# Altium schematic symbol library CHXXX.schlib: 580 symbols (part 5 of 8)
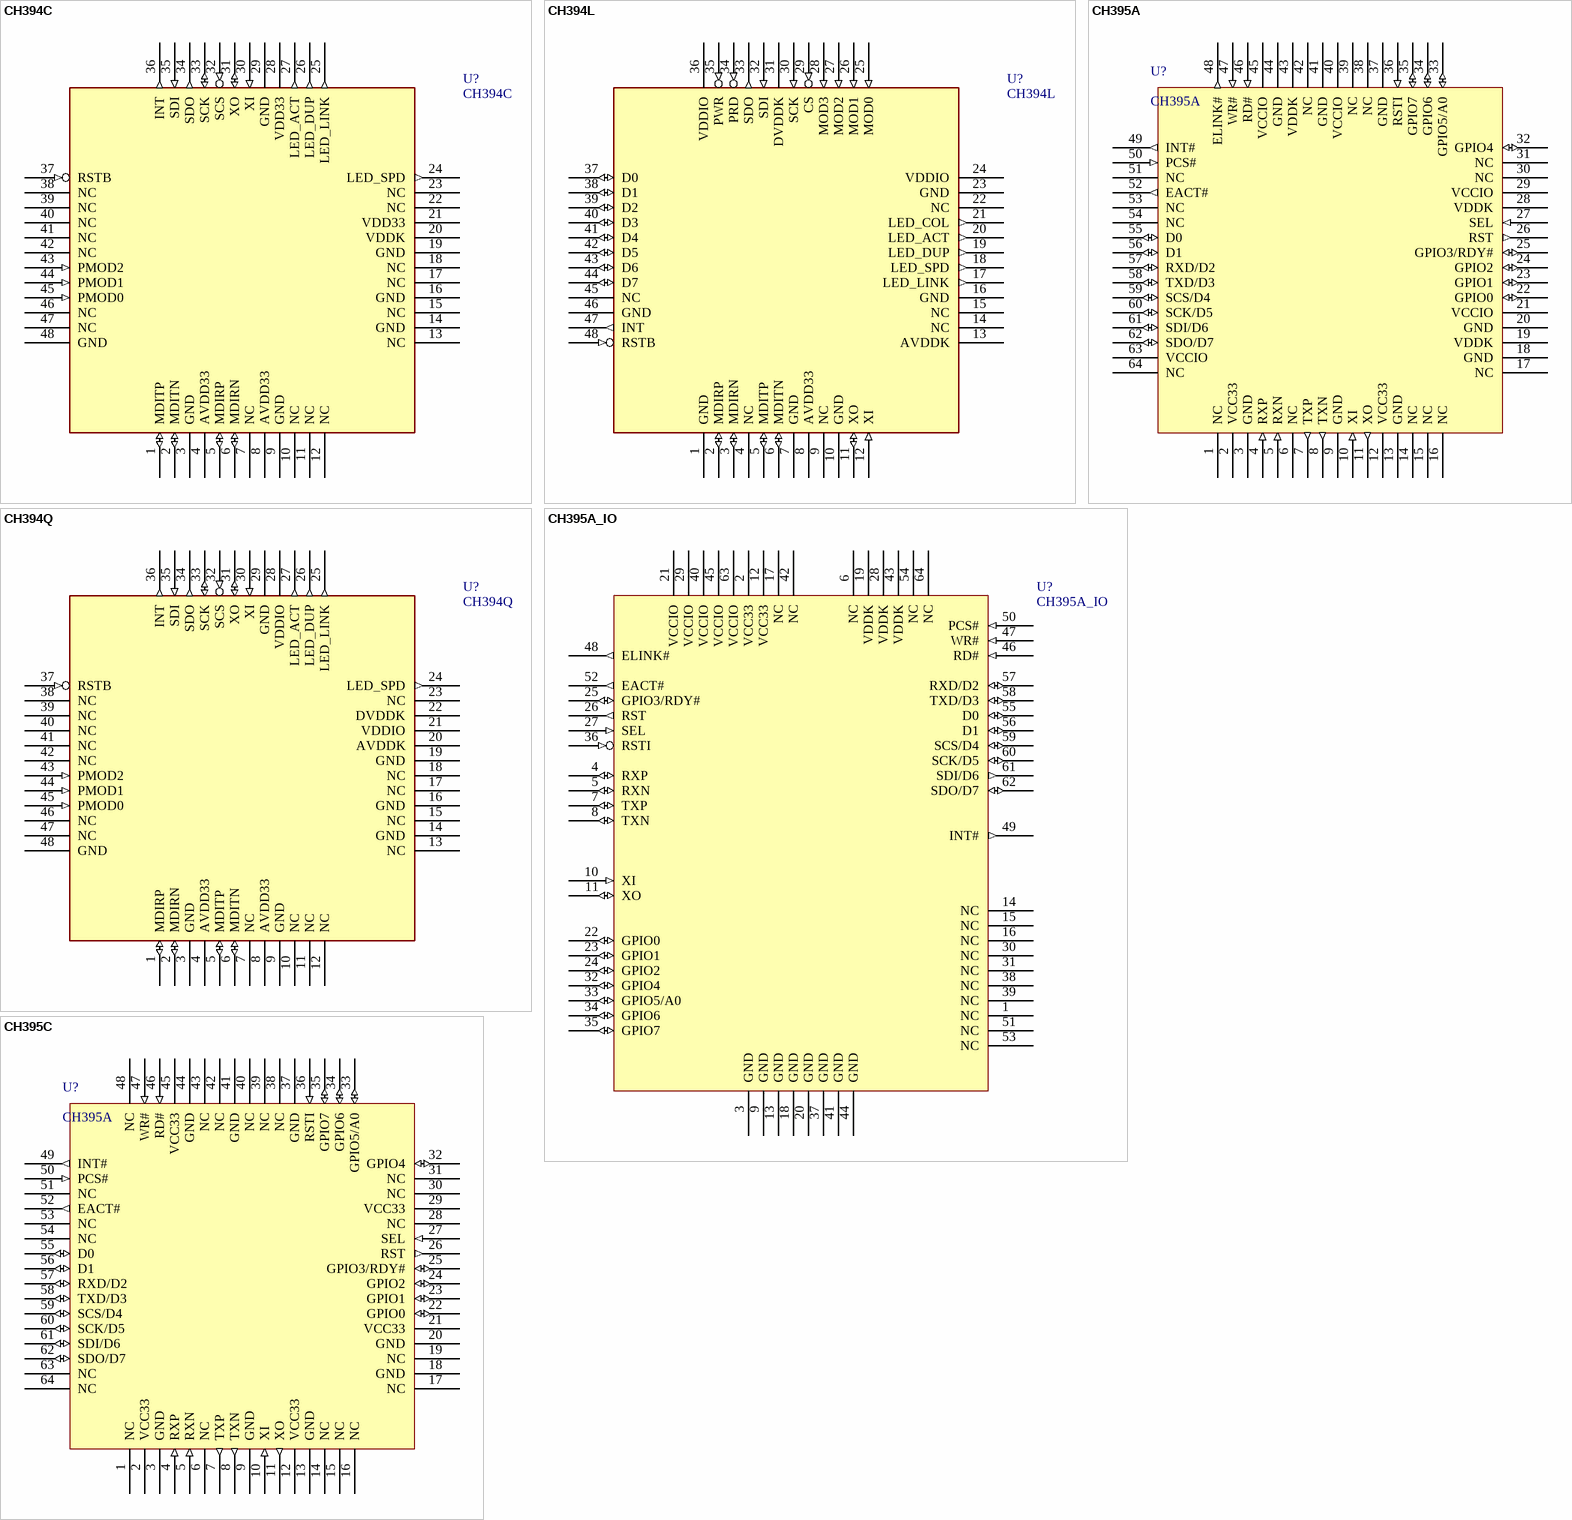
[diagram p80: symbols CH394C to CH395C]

## CH394Q
designator U?
TCP/IP embedded 10M/100Mbps ethernet controller for MCU connecting internet
footprint LQFP48 (Footprint not found)
pins: 1 MDIRP (io), 2 MDIRN (io), 3 GND (power), 4 AVDD33 (power), 5 MDITP (io), 6 MDITN (io), 7 NC, 8 AVDD33 (power), 9 GND (power), 10 NC, 11 NC, 12 NC, 13 NC, 14 GND (power), 15 NC, 16 GND (power), 17 NC, 18 NC, 19 GND (power), 20 AVDDK (power), 21 VDDIO (power), 22 DVDDK (power), 23 NC, 24 LED_SPD (out), 25 LED_LINK (out), 26 LED_DUP (out), 27 LED_ACT (out), 28 VDDIO (power), 29 GND (power), 30 XI (in), 31 XO (io), 32 SCS (in), 33 SCK (io), 34 SDO (out), 35 SDI (in), 36 INT (out), 37 RSTB (in), 38 NC, 39 NC, 40 NC, 41 NC, 42 NC, 43 PMOD2 (in), 44 PMOD1 (in), 45 PMOD0 (in), 46 NC, 47 NC, 48 GND (power)

## CH395A
designator U?
TCP/IP embedded 100Mbps ethernet controller for MCU connecting internet
footprint LQFP64M_10x10 (Footprint not found)
pins: 1 NC, 2 VCC33 (power), 3 GND, 4 RXP (in), 5 RXN (in), 6 NC, 7 TXP (out), 8 TXN (out), 9 GND (power), 10 XI (in), 11 XO (out), 12 VCC33 (power), 13 GND (power), 14 NC, 15 NC, 16 NC, 17 NC, 18 GND (power), 19 VDDK (power), 20 GND (power), 21 VCCIO (power), 22 GPIO0 (io), 23 GPIO1 (io), 24 GPIO2 (io), 25 GPIO3/RDY# (io), 26 RST (out), 27 SEL (in), 28 VDDK (power), 29 VCCIO (power), 30 NC, 31 NC, 32 GPIO4 (io), 33 GPIO5/A0 (io), 34 GPIO6 (io), 35 GPIO7 (io), 36 RSTI (in), 37 GND (power), 38 NC, 39 NC, 40 VCCIO (power), 41 GND (power), 42 NC, 43 VDDK (power), 44 GND (power), 45 VCCIO (power), 46 RD# (in), 47 WR# (in), 48 ELINK# (out), 49 INT# (out), 50 PCS# (in), 51 NC, 52 EACT# (out), 53 NC, 54 NC, 55 D0 (io), 56 D1 (io), 57 RXD/D2 (io), 58 TXD/D3 (io), 59 SCS/D4 (io), 60 SCK/D5 (io), 61 SDI/D6 (io), 62 SDO/D7 (io), 63 VCCIO (power), 64 NC

## CH395A_IO
designator U?
TCP/IP embedded 100Mbps ethernet controller for MCU connecting internet
footprint LQFP64M_10X10
pins: 1 NC, 2 VCC33 (power), 3 GND (power), 4 RXP (io), 5 RXN (io), 6 NC, 7 TXP (io), 8 TXN (io), 9 GND (power), 10 XI (in), 11 XO (io), 12 VCC33 (power), 13 GND (power), 14 NC, 15 NC, 16 NC, 17 NC, 18 GND (power), 19 VDDK (power), 20 GND (power), 21 VCCIO (power), 22 GPIO0 (io), 23 GPIO1 (io), 24 GPIO2 (io), 25 GPIO3/RDY# (io), 26 RST (out), 27 SEL (in), 28 VDDK (power), 29 VCCIO (power), 30 NC, 31 NC, 32 GPIO4 (io), 33 GPIO5/A0 (io), 34 GPIO6 (io), 35 GPIO7 (io), 36 RSTI (in), 37 GND (power), 38 NC, 39 NC, 40 VCCIO (power), 41 GND (power), 42 NC, 43 VDDK (power), 44 GND (power), 45 VCCIO (power), 46 RD# (in), 47 WR# (in), 48 ELINK# (out), 49 INT# (out), 50 PCS# (in), 51 NC, 52 EACT# (out), 53 NC, 54 NC, 55 D0 (io), 56 D1 (io), 57 RXD/D2 (io), 58 TXD/D3 (io), 59 SCS/D4 (io), 60 SCK/D5 (io), 61 SDI/D6 (out), 62 SDO/D7 (io), 63 VCCIO (power), 64 NC

## CH395C
designator U?, comment CH395A
TCP/IP embedded 100Mbps ethernet controller for MCU connecting internet
footprint LQFP64M_10x10 (Footprint not found)
pins: 1 NC, 2 VCC33 (power), 3 GND, 4 RXP (in), 5 RXN (in), 6 NC, 7 TXP (out), 8 TXN (out), 9 GND (power), 10 XI (in), 11 XO (out), 12 VCC33 (power), 13 GND (power), 14 NC, 15 NC, 16 NC, 17 NC, 18 GND (power), 19 NC, 20 GND (power), 21 VCC33 (power), 22 GPIO0 (io), 23 GPIO1 (io), 24 GPIO2 (io), 25 GPIO3/RDY# (io), 26 RST (out), 27 SEL (in), 28 NC, 29 VCC33 (power), 30 NC, 31 NC, 32 GPIO4 (io), 33 GPIO5/A0 (io), 34 GPIO6 (io), 35 GPIO7 (io), 36 RSTI (in), 37 GND (power), 38 NC, 39 NC, 40 NC, 41 GND (power), 42 NC, 43 NC, 44 GND (power), 45 VCC33 (power), 46 RD# (in), 47 WR# (in), 48 NC, 49 INT# (out), 50 PCS# (in), 51 NC, 52 EACT# (out), 53 NC, 54 NC, 55 D0 (io), 56 D1 (io), 57 RXD/D2 (io), 58 TXD/D3 (io), 59 SCS/D4 (io), 60 SCK/D5 (io), 61 SDI/D6 (io), 62 SDO/D7 (io), 63 NC, 64 NC

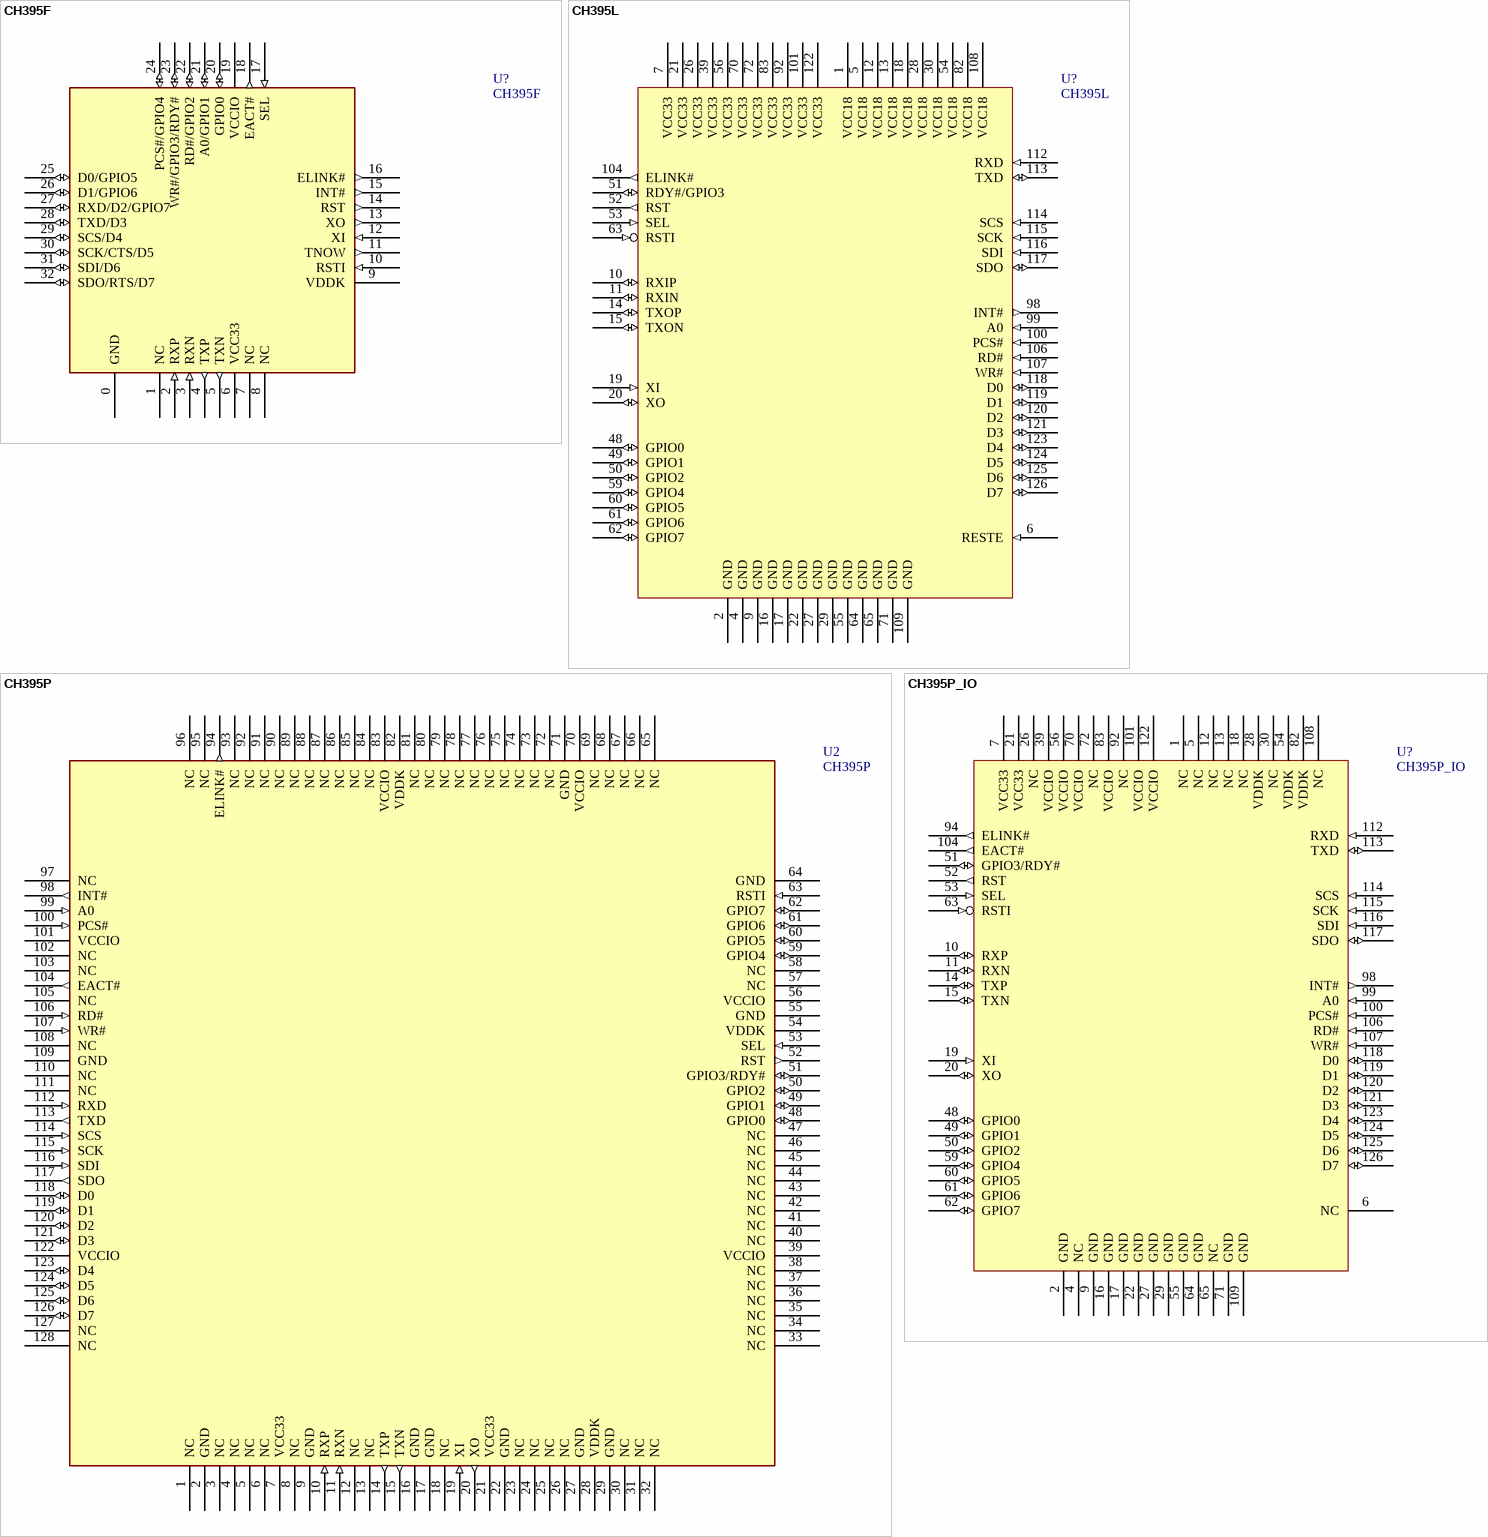
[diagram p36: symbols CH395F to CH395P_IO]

## CH395F
designator U?
TCP/IP embedded 100Mbps ethernet controller for MCU connecting internet
footprint QFN32_4X4 (Footprint not found)
pins: 0 GND (power), 1 NC (power), 2 RXP (in), 3 RXN (in), 4 TXP (out), 5 TXN (out), 6 VCC33 (power), 7 NC, 8 NC, 9 VDDK (power), 10 RSTI (in), 11 TNOW (out), 12 XI (in), 13 XO (out), 14 RST (out), 15 INT# (out), 16 ELINK# (out), 17 SEL (in), 18 EACT# (out), 19 VCCIO (power), 20 GPIO0 (io), 21 A0/GPIO1 (io), 22 RD#/GPIO2 (io), 23 WR#/GPIO3/RDY# (io), 24 PCS#/GPIO4 (io), 25 D0/GPIO5 (io), 26 D1/GPIO6 (io), 27 RXD/D2/GPIO7 (io), 28 TXD/D3 (io), 29 SCS/D4 (io), 30 SCK/CTS/D5 (io), 31 SDI/D6 (io), 32 SDO/RTS/D7 (io)

## CH395L
designator U?
TCP/IP embedded 100Mbps ethernet controller for MCU connecting internet
footprint LQFP128
pins: 1 VCC18 (power), 2 GND (power), 4 GND (power), 5 VCC18 (power), 6 RESTE (in), 7 VCC33 (power), 9 GND (power), 10 RXIP (io), 11 RXIN (io), 12 VCC18 (power), 13 VCC18 (power), 14 TXOP (io), 15 TXON (io), 16 GND (power), 17 GND (power), 18 VCC18 (power), 19 XI (in), 20 XO (io), 21 VCC33 (power), 22 GND (power), 26 VCC33 (power), 27 GND (power), 28 VCC18 (power), 29 GND (power), 30 VCC18 (power), 39 VCC33 (power), 48 GPIO0 (io), 49 GPIO1 (io), 50 GPIO2 (io), 51 RDY#/GPIO3 (io), 52 RST (out), 53 SEL (in), 54 VCC18 (power), 55 GND (power), 56 VCC33 (power), 59 GPIO4 (io), 60 GPIO5 (io), 61 GPIO6 (io), 62 GPIO7 (io), 63 RSTI (in), 64 GND (power), 65 GND (power), 70 VCC33 (power), 71 GND (power), 72 VCC33 (power), 82 VCC18 (power), 83 VCC33 (power), 92 VCC33 (power), 98 INT# (out), 99 A0 (in), 100 PCS# (in), 101 VCC33 (power), 104 ELINK# (out), 106 RD# (in), 107 WR# (in), 108 VCC18 (power), 109 GND (power), 112 RXD (in), 113 TXD (io), 114 SCS (in), 115 SCK (in), 116 SDI (in), 117 SDO (io), 118 D0 (io), 119 D1 (io), 120 D2 (io), 121 D3 (io), 122 VCC33 (power), 123 D4 (io), 124 D5 (io), 125 D6 (io), 126 D7 (io)

## CH395P
designator U2
TCP/IP embedded 100Mbps ethernet controller for MCU connecting internet
footprint LQFP128 (Footprint not found)
pins: 1 NC, 2 GND (power), 3 NC, 4 NC, 5 NC, 6 NC (power), 7 VCC33 (power), 8 NC, 9 GND (power), 10 RXP (in), 11 RXN (in), 12 NC, 13 NC, 14 TXP (out), 15 TXN (out), 16 GND (power), 17 GND (power), 18 NC, 19 XI (in), 20 XO (out), 21 VCC33 (power), 22 GND (power), 23 NC, 24 NC, 25 NC, 26 NC, 27 GND (power), 28 VDDK (power), 29 GND (power), 30 NC, 31 NC, 32 NC, 33 NC, 34 NC, 35 NC, 36 NC, 37 NC, 38 NC, 39 VCCIO (power), 40 NC, 41 NC, 42 NC, 43 NC, 44 NC, 45 NC, 46 NC, 47 NC, 48 GPIO0 (io), 49 GPIO1 (io), 50 GPIO2 (io), 51 GPIO3/RDY# (io), 52 RST (out), 53 SEL (in), 54 VDDK (power), 55 GND (power), 56 VCCIO (power), 57 NC, 58 NC, 59 GPIO4 (io), 60 GPIO5 (io), 61 GPIO6 (io), 62 GPIO7 (io), 63 RSTI (in), 64 GND (power), 65 NC, 66 NC, 67 NC, 68 NC, 69 NC, 70 VCCIO (power), 71 GND (power), 72 NC, 73 NC, 74 NC, 75 NC, 76 NC, 77 NC, 78 NC, 79 NC, 80 NC, 81 NC, 82 VDDK (power), 83 VCCIO (power), 84 NC, 85 NC, 86 NC, 87 NC, 88 NC, 89 NC, 90 NC, 91 NC, 92 NC, 93 NC, 94 ELINK# (out), 95 NC, 96 NC, 97 NC, 98 INT# (out), 99 A0 (in), 100 PCS# (in), 101 VCCIO (power), 102 NC, 103 NC, 104 EACT# (out), 105 NC, 106 RD# (in), 107 WR# (in), 108 NC, 109 GND (power), 110 NC, 111 NC, 112 RXD (in), 113 TXD (out), 114 SCS (in), 115 SCK (in), 116 SDI (in), 117 SDO (out), 118 D0 (io), 119 D1 (io), 120 D2 (io), 121 D3 (io), 122 VCCIO (power), 123 D4 (io), 124 D5 (io), 125 D6 (io), 126 D7 (io), 127 NC, 128 NC

## CH395P_IO
designator U?
TCP/IP embedded 100Mbps ethernet controller for MCU connecting internet
footprint LQFP128
pins: 1 NC, 2 GND (power), 4 NC, 5 NC, 6 NC (power), 7 VCC33 (power), 9 GND (power), 10 RXP (io), 11 RXN (io), 12 NC, 13 NC, 14 TXP (io), 15 TXN (io), 16 GND (power), 17 GND (power), 18 NC, 19 XI (in), 20 XO (io), 21 VCC33 (power), 22 GND (power), 26 NC, 27 GND (power), 28 VDDK (power), 29 GND (power), 30 NC, 39 VCCIO (power), 48 GPIO0 (io), 49 GPIO1 (io), 50 GPIO2 (io), 51 GPIO3/RDY# (io), 52 RST (out), 53 SEL (in), 54 VDDK (power), 55 GND (power), 56 VCCIO (power), 59 GPIO4 (io), 60 GPIO5 (io), 61 GPIO6 (io), 62 GPIO7 (io), 63 RSTI (in), 64 GND (power), 65 NC, 70 VCCIO (power), 71 GND (power), 72 NC, 82 VDDK (power), 83 VCCIO (power), 92 NC, 94 ELINK# (out), 98 INT# (out), 99 A0 (in), 100 PCS# (in), 101 VCCIO (power), 104 EACT# (out), 106 RD# (in), 107 WR# (in), 108 NC, 109 GND (power), 112 RXD (in), 113 TXD (io), 114 SCS (in), 115 SCK (in), 116 SDI (in), 117 SDO (io), 118 D0 (io), 119 D1 (io), 120 D2 (io), 121 D3 (io), 122 VCCIO (power), 123 D4 (io), 124 D5 (io), 125 D6 (io), 126 D7 (io)

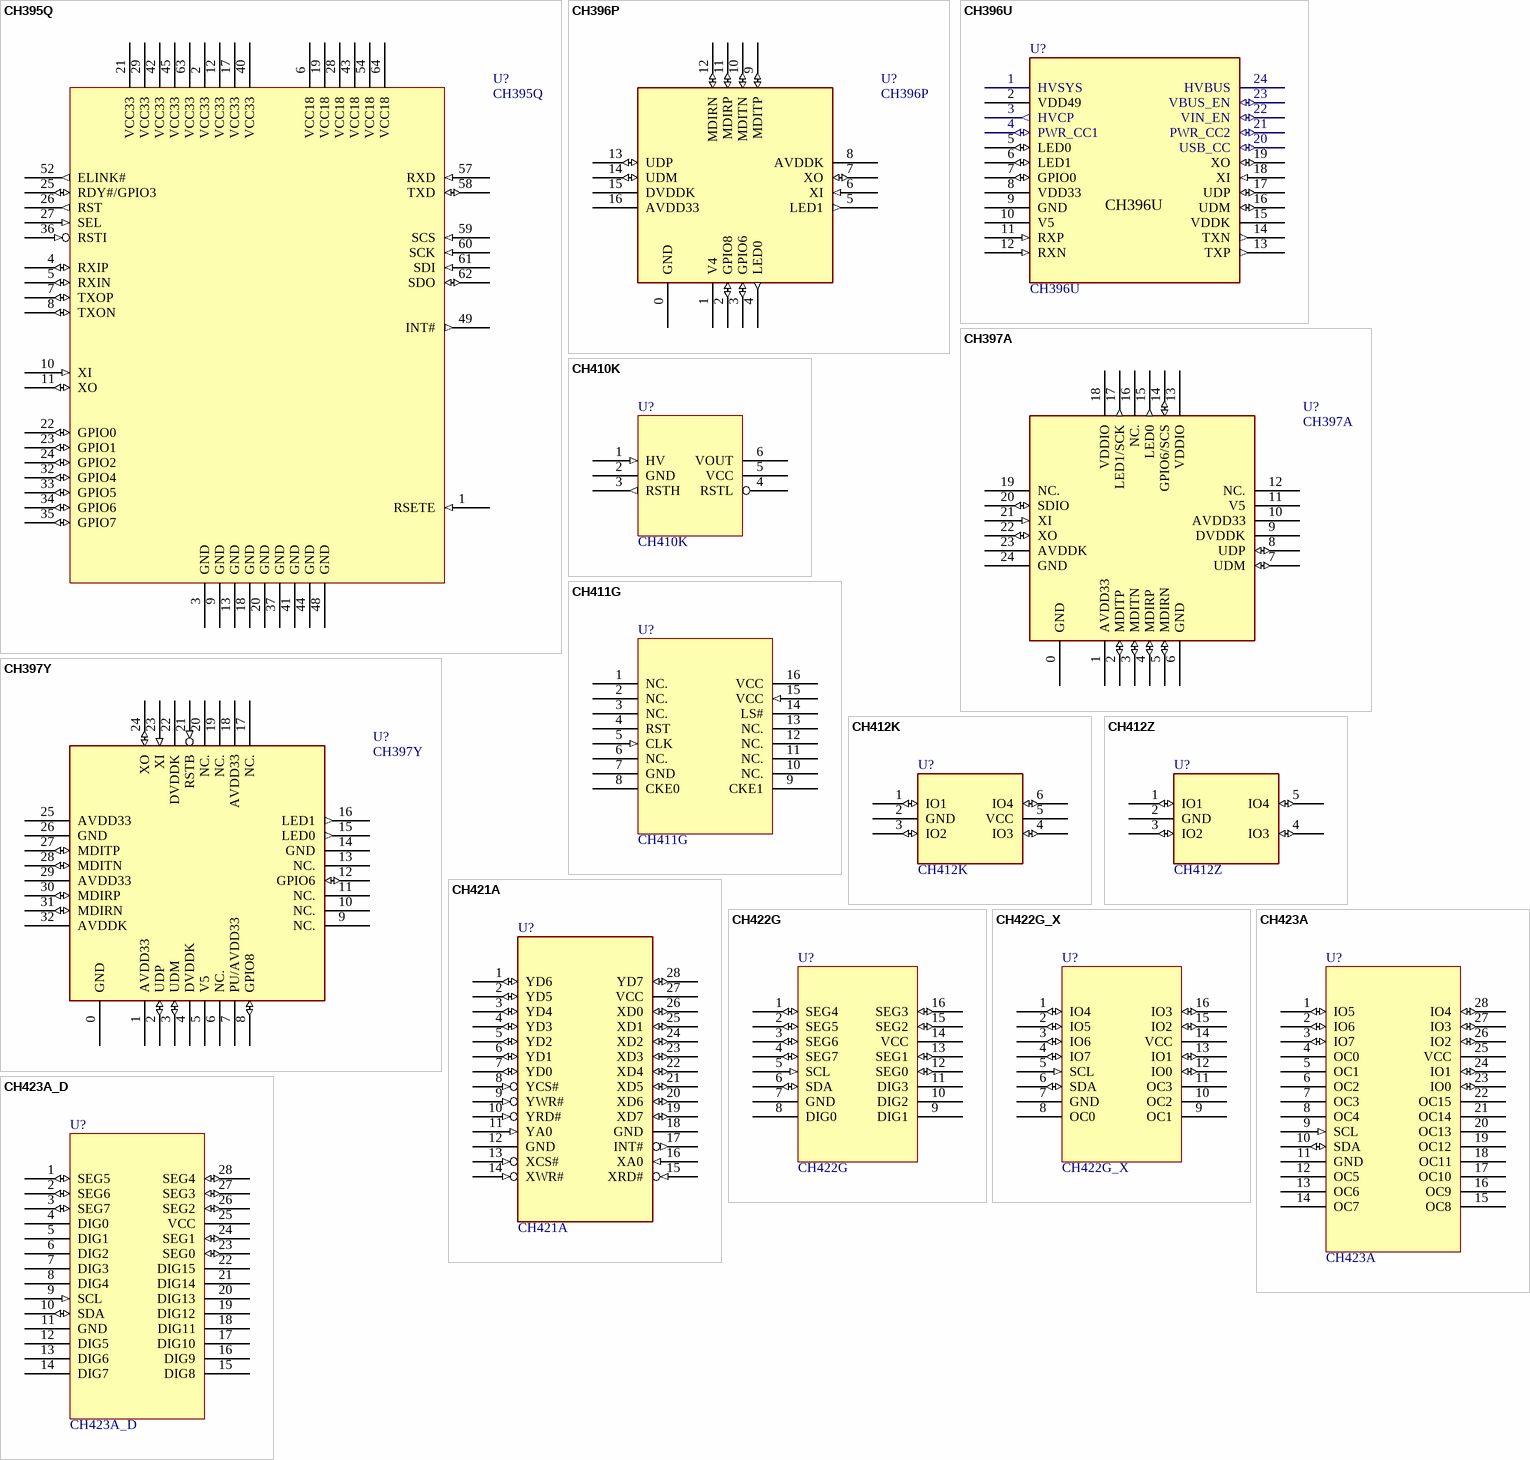
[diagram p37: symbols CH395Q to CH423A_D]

## CH395Q
designator U?
TCP/IP embedded 100Mbps ethernet controller for MCU connecting internet
footprint LQFP64M_10X10
pins: 1 RSETE (in), 2 VCC33 (power), 3 GND (power), 4 RXIP (io), 5 RXIN (io), 6 VCC18 (power), 7 TXOP (io), 8 TXON (io), 9 GND (power), 10 XI (in), 11 XO (io), 12 VCC33 (power), 13 GND (power), 17 VCC33 (power), 18 GND (power), 19 VCC18 (power), 20 GND (power), 21 VCC33 (power), 22 GPIO0 (io), 23 GPIO1 (io), 24 GPIO2 (io), 25 RDY#/GPIO3 (io), 26 RST (out), 27 SEL (in), 28 VCC18 (power), 29 VCC33 (power), 32 GPIO4 (io), 33 GPIO5 (io), 34 GPIO6 (io), 35 GPIO7 (io), 36 RSTI (in), 37 GND (power), 40 VCC33 (power), 41 GND (power), 42 VCC33 (power), 43 VCC18 (power), 44 GND (power), 45 VCC33 (power), 48 GND (power), 49 INT# (out), 52 ELINK# (out), 54 VCC18 (power), 57 RXD (in), 58 TXD (io), 59 SCS (in), 60 SCK (in), 61 SDI (in), 62 SDO (io), 63 VCC33 (power), 64 VCC18 (power)

## CH396P
designator U?
USB2.0 to 10/100M Fast Ethernet with Driver Flash
footprint QFN16_3X3
pins: 0 GND (power), 1 V4 (power), 2 GPIO8 (io), 3 GPIO6 (io), 4 LED0 (out), 5 LED1 (out), 6 XI (in), 7 XO (io), 8 AVDDK (power), 9 MDITP (io), 10 MDITN (io), 11 MDIRP (io), 12 MDIRN (io), 13 UDP (io), 14 UDM (io), 15 DVDDK (power), 16 AVDD33 (power)

## CH396U
designator U?
RISC-V MCU with USB OTG 2.0 & 100Mbps Ethernet & Type-C/PD 28V
footprint QSOP24
pins: 1 HVSYS (power), 2 VDD49 (power), 3 HVCP (out), 4 PWR_CC1 (io), 5 LED0 (io), 6 LED1 (io), 7 GPIO0 (io), 8 VDD33 (power), 9 GND (power), 10 V5 (power), 11 RXP (in), 12 RXN (in), 13 TXP (out), 14 TXN (out), 15 VDDK (power), 16 UDM (io), 17 UDP (io), 18 XI (in), 19 XO (io), 20 USB_CC (io), 21 PWR_CC2 (io), 22 VIN_EN (io), 23 VBUS_EN (io), 24 HVBUS (power)

## CH397A
designator U?
USB2.0 to 10/100M Fast Ethernet with Driver Flash
footprint QFN24_4X4
pins: 0 GND (power), 1 AVDD33 (power), 2 MDITP (io), 3 MDITN (io), 4 MDIRP (io), 5 MDIRN (io), 6 GND (power), 7 UDM (io), 8 UDP (io), 9 DVDDK (power), 10 AVDD33 (power), 11 V5 (power), 12 NC., 13 VDDIO (power), 14 GPIO6/SCS (io), 15 LED0 (out), 16 NC., 17 LED1/SCK (out), 18 VDDIO (power), 19 NC., 20 SDIO (io), 21 XI (in), 22 XO (io), 23 AVDDK (power), 24 GND (power)

## CH397Y
designator U?
USB2.0 to 10/100M Fast Ethernet with Driver Flash
footprint QFN32_4X4
pins: 0 GND (power), 1 AVDD33 (power), 2 UDP (io), 3 UDM (io), 4 DVDDK (power), 5 V5 (power), 6 NC., 7 PU/AVDD33 (power), 8 GPIO8 (io), 9 NC., 10 NC., 11 NC., 12 GPIO6 (io), 13 NC., 14 GND (power), 15 LED0 (out), 16 LED1 (out), 17 NC., 18 AVDD33 (power), 19 NC., 20 NC., 21 RSTB (in), 22 DVDDK (power), 23 XI (in), 24 XO (io), 25 AVDD33 (power), 26 GND (power), 27 MDITP (io), 28 MDITN (io), 29 AVDD33 (power), 30 MDIRP (io), 31 MDIRN (io), 32 AVDDK (power)

## CH410K
designator U?
PowerOnReset & LowVoltageReset, voltage monitor
footprint SOT-363
pins: 1 HV (in), 2 GND (power), 3 RSTH (out), 4 RSTL (oc), 5 VCC (power), 6 VOUT (power)

## CH411G
designator U?
Work state monitor
footprint SOP16
pins: 1 NC., 2 NC., 3 NC., 4 RST (oc), 5 CLK (in), 6 NC., 7 GND (power), 8 CKE0 (oc), 9 CKE1 (oc), 10 NC., 11 NC., 12 NC., 13 NC., 14 LS# (oc), 15 VCC (in), 16 VCC (power)

## CH412K
designator U?
Qaud ESD protect, high speed
footprint SOT-363
pins: 1 IO1 (io), 2 GND (power), 3 IO2 (io), 4 IO3 (io), 5 VCC (power), 6 IO4 (io)

## CH412Z
designator U?
Quad ESD protect, low speed
footprint SOT-353
pins: 1 IO1 (io), 2 GND (power), 3 IO2 (io), 4 IO3 (io), 5 IO4 (io)

## CH421A
designator U?
Dual port buffer, 66 byte
footprint SOP28
pins: 1 YD6 (io), 2 YD5 (io), 3 YD4 (io), 4 YD3 (io), 5 YD2 (io), 6 YD1 (io), 7 YD0 (io), 8 YCS# (in), 9 YWR# (in), 10 YRD# (in), 11 YA0 (in), 12 GND (power), 13 XCS# (in), 14 XWR# (in), 15 XRD# (in), 16 XA0 (in), 17 INT# (out), 18 GND (power), 19 XD7 (io), 20 XD6 (io), 21 XD5 (io), 22 XD4 (io), 23 XD3 (io), 24 XD2 (io), 25 XD1 (io), 26 XD0 (io), 27 VCC (power), 28 YD7 (io)

## CH422G
designator U?
I2C/IIC I/O expander, GPIO, 8-Seg * 4 / 32 LEDs Drive
footprint SOP16
pins: 1 SEG4 (io), 2 SEG5 (io), 3 SEG6 (io), 4 SEG7 (io), 5 SCL (in), 6 SDA (io), 7 GND (power), 8 DIG0 (oc), 9 DIG1 (oc), 10 DIG2 (oc), 11 DIG3 (oc), 12 SEG0 (io), 13 SEG1 (io), 14 VCC (power), 15 SEG2 (io), 16 SEG3 (io)

## CH422G_X
designator U?
I2C/IIC I/O expander, 4 GPO + 8 GPIO/OC
footprint SOP16
pins: 1 IO4 (io), 2 IO5 (io), 3 IO6 (io), 4 IO7 (io), 5 SCL (in), 6 SDA (io), 7 GND (power), 8 OC0 (oc), 9 OC1 (oc), 10 OC2 (oc), 11 OC3 (oc), 12 IO0 (io), 13 IO1 (io), 14 VCC (power), 15 IO2 (io), 16 IO3 (io)

## CH423A
designator U?
I2C/IIC I/O expander, 16 GPO + 8 GPIO
footprint SOP28
footprint DIP28S
pins: 1 IO5 (io), 2 IO6 (io), 3 IO7 (io), 4 OC0 (oc), 5 OC1 (oc), 6 OC2 (oc), 7 OC3 (oc), 8 OC4 (oc), 9 SCL (in), 10 SDA (io), 11 GND (power), 12 OC5 (oc), 13 OC6 (oc), 14 OC7 (oc), 15 OC8 (oc), 16 OC9 (oc), 17 OC10 (oc), 18 OC11 (oc), 19 OC12 (oc), 20 OC13 (oc), 21 OC14 (oc), 22 OC15 (oc), 23 IO0 (io), 24 IO1 (io), 25 VCC (power), 26 IO2 (io), 27 IO3 (io), 28 IO4 (io)

## CH423A_D
designator U?
I2C/IIC I/O expander, GPIO, 8-Seg * 16 / 128 LEDs Drive
footprint SOP28
footprint DIP28S
pins: 1 SEG5 (io), 2 SEG6 (io), 3 SEG7 (io), 4 DIG0 (oc), 5 DIG1 (oc), 6 DIG2 (oc), 7 DIG3 (oc), 8 DIG4 (oc), 9 SCL (in), 10 SDA (io), 11 GND (power), 12 DIG5 (oc), 13 DIG6 (oc), 14 DIG7 (oc), 15 DIG8 (oc), 16 DIG9 (oc), 17 DIG10 (oc), 18 DIG11 (oc), 19 DIG12 (oc), 20 DIG13 (oc), 21 DIG14 (oc), 22 DIG15 (oc), 23 SEG0 (io), 24 SEG1 (io), 25 VCC (power), 26 SEG2 (io), 27 SEG3 (io), 28 SEG4 (io)

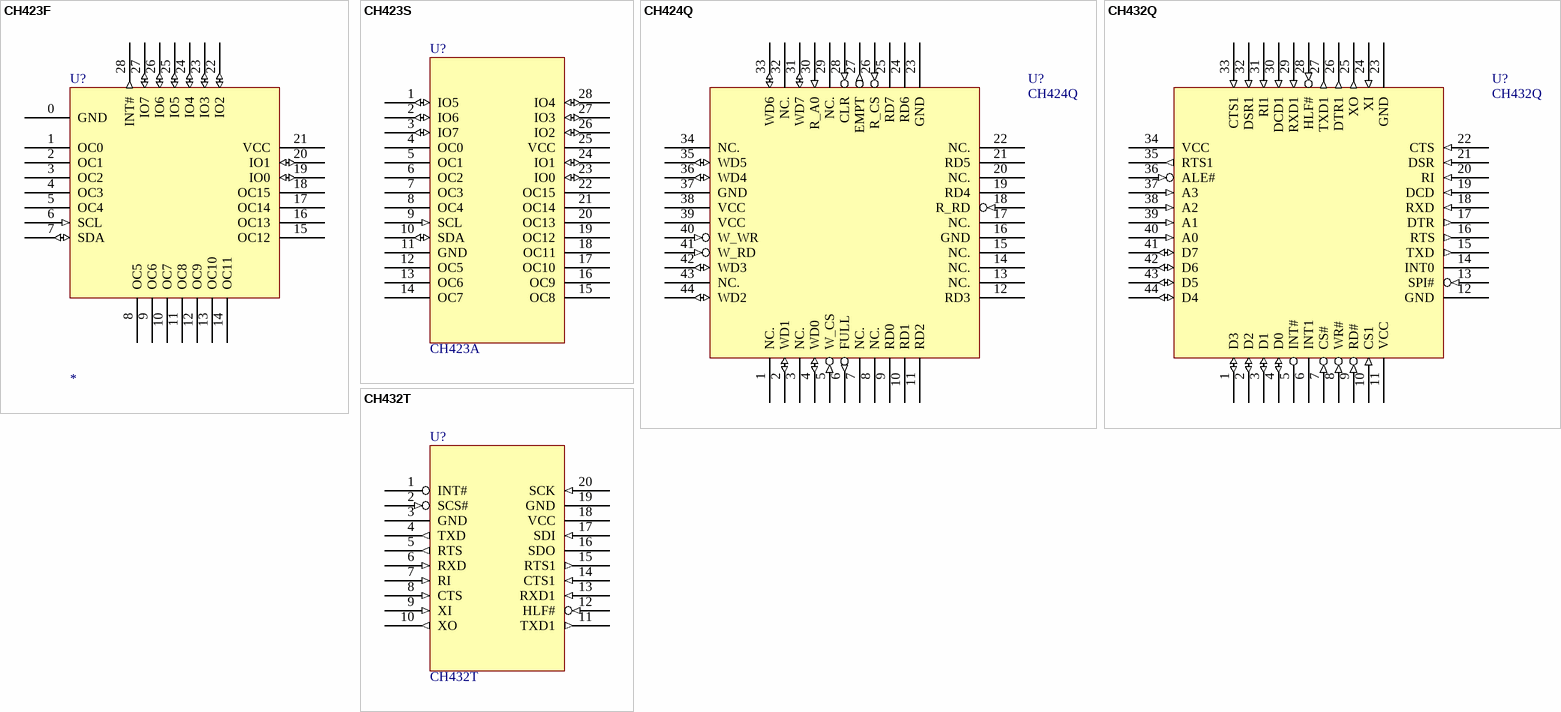
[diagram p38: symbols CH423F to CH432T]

## CH423F
designator U?
I2C/IIC I/O expander, 16 GPO + 8 GPIO
footprint QFN28_4X4 (Footprint not found)
pins: 0 GND (power), 1 OC0 (oc), 2 OC1 (oc), 3 OC2 (oc), 4 OC3 (oc), 5 OC4 (oc), 6 SCL (in), 7 SDA (io), 8 OC5 (oc), 9 OC6 (oc), 10 OC7 (oc), 11 OC8 (oc), 12 OC9 (oc), 13 OC10 (oc), 14 OC11 (oc), 15 OC12 (oc), 16 OC13 (oc), 17 OC14 (oc), 18 OC15 (oc), 19 IO0 (io), 20 IO1 (io), 21 VCC (power), 22 IO2 (io), 23 IO3 (io), 24 IO4 (io), 25 IO5 (io), 26 IO6 (io), 27 IO7 (io), 28 INT# (out)

## CH423S
designator U?, comment CH423A
I2C/IIC I/O expander, 16 GPO + 8 GPIO
footprint SOP28
pins: 1 IO5 (io), 2 IO6 (io), 3 IO7 (io), 4 OC0 (oc), 5 OC1 (oc), 6 OC2 (oc), 7 OC3 (oc), 8 OC4 (oc), 9 SCL (in), 10 SDA (io), 11 GND (power), 12 OC5 (oc), 13 OC6 (oc), 14 OC7 (oc), 15 OC8 (oc), 16 OC9 (oc), 17 OC10 (oc), 18 OC11 (oc), 19 OC12 (oc), 20 OC13 (oc), 21 OC14 (oc), 22 OC15 (oc), 23 IO0 (io), 24 IO1 (io), 25 VCC (power), 26 IO2 (io), 27 IO3 (io), 28 IO4 (io)

## CH424Q
designator U?
FIFO, 4K byte * 8 bit
footprint LQFP44
pins: 1 NC., 2 WD1 (io), 3 NC., 4 WD0 (io), 5 W_CS (in), 6 FULL (out), 7 NC., 8 NC., 9 RD0 (hiz), 10 RD1 (hiz), 11 RD2 (hiz), 12 RD3 (hiz), 13 NC., 14 NC., 15 NC., 16 GND (power), 17 NC., 18 R_RD (in), 19 RD4 (hiz), 20 NC., 21 RD5 (hiz), 22 NC., 23 GND (power), 24 RD6 (hiz), 25 RD7 (hiz), 26 R_CS (in), 27 EMPT (out), 28 CLR (in), 29 NC., 30 R_A0 (in), 31 WD7 (io), 32 NC., 33 WD6 (io), 34 NC., 35 WD5 (io), 36 WD4 (io), 37 GND (power), 38 VCC (power), 39 VCC (power), 40 W_WR (in), 41 W_RD (in), 42 WD3 (io), 43 NC., 44 WD2 (io)

## CH432Q
designator U?
Dual 16C550 UART with IrDA, parallel / SPI
footprint LQFP44
pins: 1 D3 (io), 2 D2 (io), 3 D1 (io), 4 D0 (io), 5 INT# (oc), 6 INT1 (hiz), 7 CS# (in), 8 WR# (in), 9 RD# (in), 10 CS1 (in), 11 VCC (power), 12 GND (power), 13 SPI# (in), 14 INT0 (hiz), 15 TXD (out), 16 RTS (out), 17 DTR (out), 18 RXD (in), 19 DCD (in), 20 RI (in), 21 DSR (in), 22 CTS (in), 23 GND (power), 24 XI (in), 25 XO (out), 26 DTR1 (out), 27 TXD1 (out), 28 HLF# (in), 29 RXD1 (in), 30 DCD1 (in), 31 RI1 (in), 32 DSR1 (in), 33 CTS1 (in), 34 VCC (power), 35 RTS1 (out), 36 ALE# (in), 37 A3 (in), 38 A2 (in), 39 A1 (in), 40 A0 (in), 41 D7 (io), 42 D6 (io), 43 D5 (io), 44 D4 (io)

## CH432T
designator U?
SPI Dual 16C550 UART with IrDA
footprint SSOP20
pins: 1 INT# (oc), 2 SCS# (in), 3 GND (power), 4 TXD (out), 5 RTS (out), 6 RXD (in), 7 RI (in), 8 CTS (in), 9 XI (in), 10 XO (out), 11 TXD1 (out), 12 HLF# (in), 13 RXD1 (in), 14 CTS1 (in), 15 RTS1 (out), 16 SDO (hiz), 17 SDI (in), 18 VCC (power), 19 GND (power), 20 SCK (in)

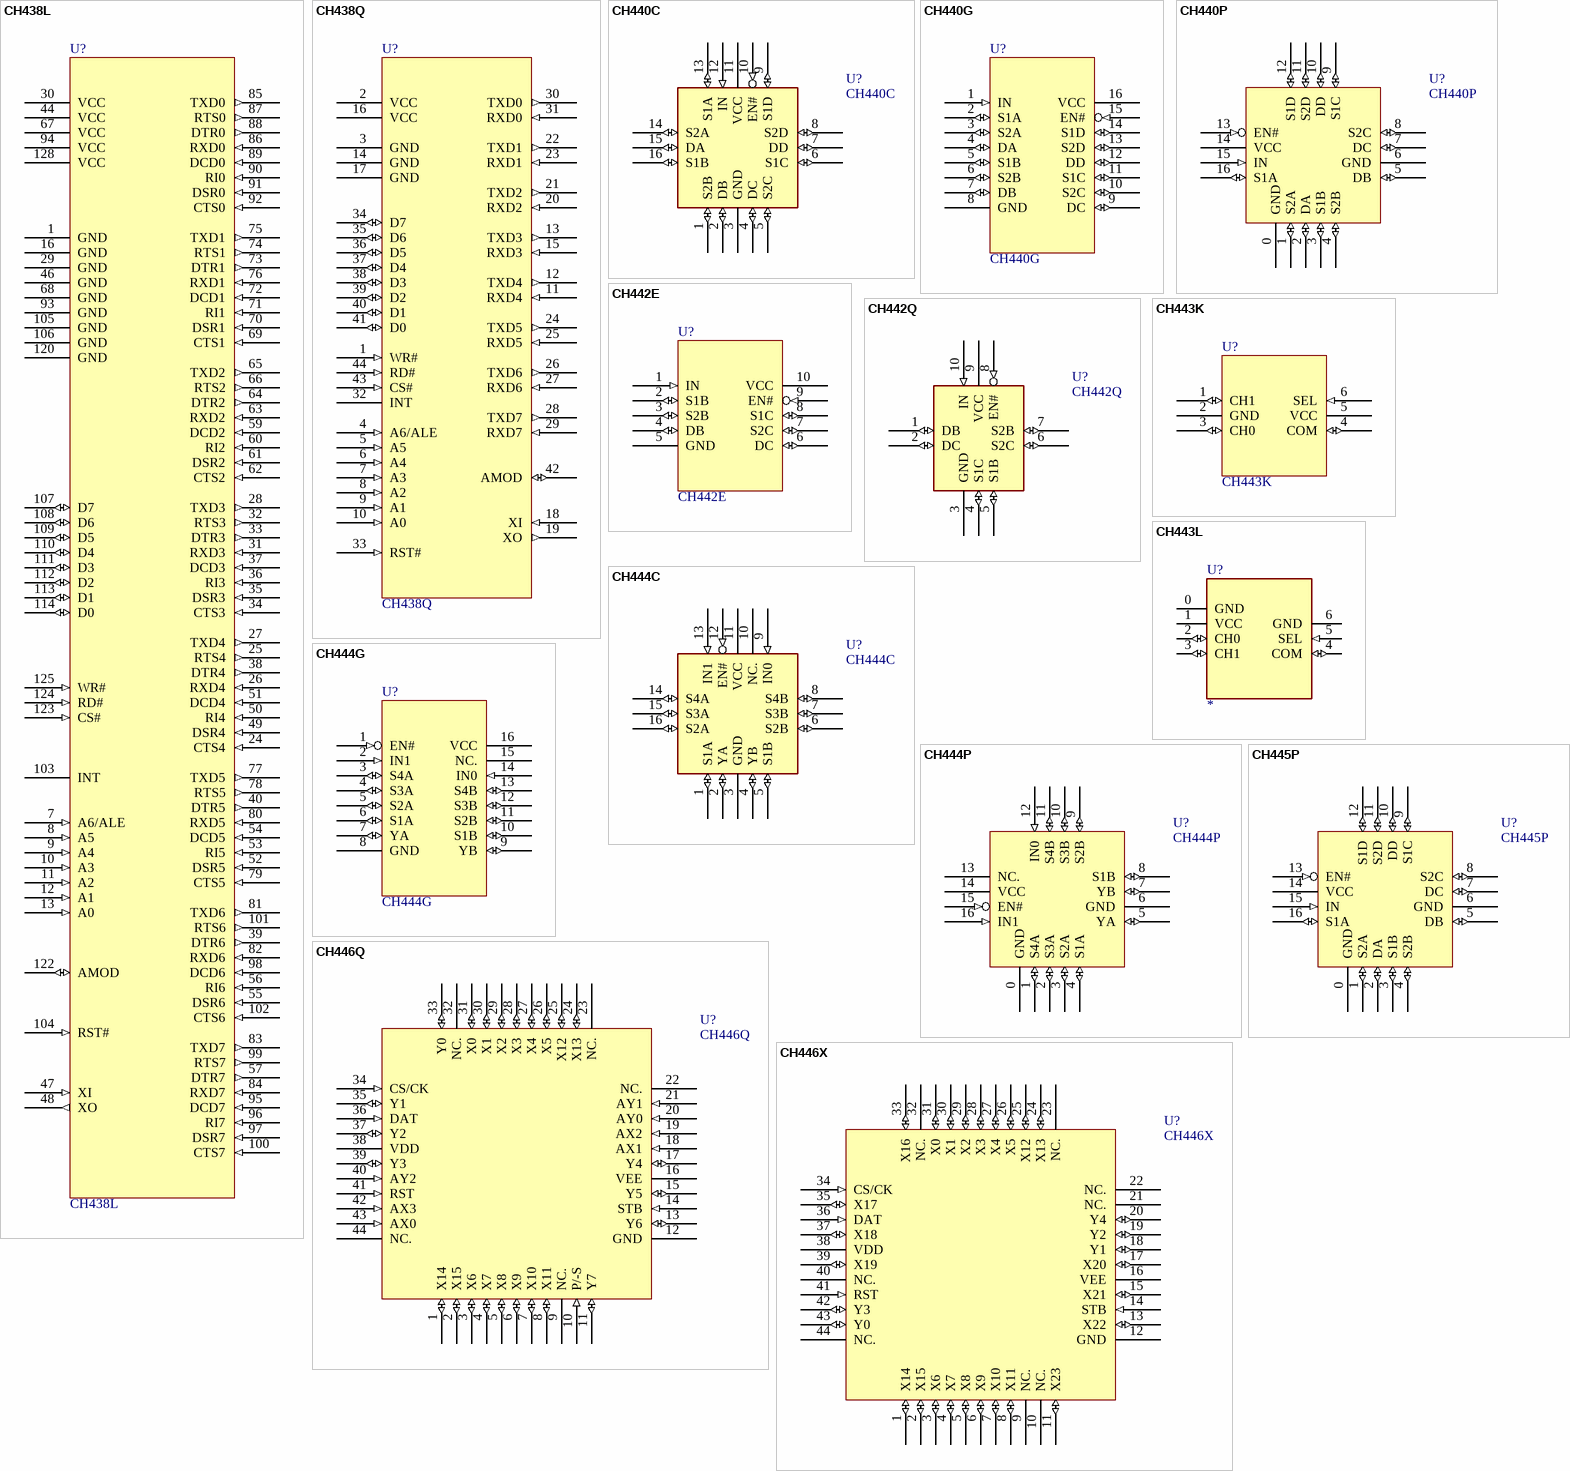
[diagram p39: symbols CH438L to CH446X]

## CH438L
designator U?
Parallel to 8S: Oct 16C550 UART with 128 byte FIFO, TTL Serial*8
footprint LQFP128
pins: 1 GND (power), 7 A6/ALE (in), 8 A5 (in), 9 A4 (in), 10 A3 (in), 11 A2 (in), 12 A1 (in), 13 A0 (in), 16 GND (power), 24 CTS4 (in), 25 RTS4 (out), 26 RXD4 (in), 27 TXD4 (out), 28 TXD3 (out), 29 GND (power), 30 VCC (power), 31 RXD3 (in), 32 RTS3 (out), 33 DTR3 (out), 34 CTS3 (in), 35 DSR3 (in), 36 RI3 (in), 37 DCD3 (in), 38 DTR4 (out), 39 DTR6 (out), 40 DTR5 (out), 44 VCC (power), 46 GND (power), 47 XI (in), 48 XO (out), 49 DSR4 (in), 50 RI4 (in), 51 DCD4 (in), 52 DSR5 (in), 53 RI5 (in), 54 DCD5 (in), 55 DSR6 (in), 56 RI6 (in), 57 DTR7 (out), 59 DCD2 (in), 60 RI2 (in), 61 DSR2 (in), 62 CTS2 (in), 63 RXD2 (in), 64 DTR2 (out), 65 TXD2 (out), 66 RTS2 (out), 67 VCC (power), 68 GND (power), 69 CTS1 (in), 70 DSR1 (in), 71 RI1 (in), 72 DCD1 (in), 73 DTR1 (out), 74 RTS1 (out), 75 TXD1 (out), 76 RXD1 (in), 77 TXD5 (out), 78 RTS5 (out), 79 CTS5 (in), 80 RXD5 (in), 81 TXD6 (out), 82 RXD6 (in), 83 TXD7 (out), 84 RXD7 (in), 85 TXD0 (out), 86 RXD0 (in), 87 RTS0 (out), 88 DTR0 (out), 89 DCD0 (in), 90 RI0 (in), 91 DSR0 (in), 92 CTS0 (in), 93 GND (power), 94 VCC (power), 95 DCD7 (in), 96 RI7 (in), 97 DSR7 (in), 98 DCD6 (in), 99 RTS7 (out), 100 CTS7 (in), 101 RTS6 (out), 102 CTS6 (in), 103 INT (oc), 104 RST# (in), 105 GND (power), 106 GND (power), 107 D7 (io), 108 D6 (io), 109 D5 (io), 110 D4 (io), 111 D3 (io), 112 D2 (io), 113 D1 (io), 114 D0 (io), 120 GND (power), 122 AMOD (io), 123 CS# (in), 124 RD# (in), 125 WR# (in), 128 VCC (power)

## CH438Q
designator U?
Parallel to 8S: Oct 16C550 UART with 128 byte FIFO, TTL Serial*8
footprint LQFP44
pins: 1 WR# (in), 2 VCC (power), 3 GND (power), 4 A6/ALE (in), 5 A5 (in), 6 A4 (in), 7 A3 (in), 8 A2 (in), 9 A1 (in), 10 A0 (in), 11 RXD4 (in), 12 TXD4 (out), 13 TXD3 (out), 14 GND (power), 15 RXD3 (in), 16 VCC (power), 17 GND (power), 18 XI (in), 19 XO (out), 20 RXD2 (in), 21 TXD2 (out), 22 TXD1 (out), 23 RXD1 (in), 24 TXD5 (out), 25 RXD5 (in), 26 TXD6 (out), 27 RXD6 (in), 28 TXD7 (out), 29 RXD7 (in), 30 TXD0 (out), 31 RXD0 (in), 32 INT (oc), 33 RST# (in), 34 D7 (io), 35 D6 (io), 36 D5 (io), 37 D4 (io), 38 D3 (io), 39 D2 (io), 40 D1 (io), 41 D0 (io), 42 AMOD (io), 43 CS# (in), 44 RD# (in)

## CH440C
designator U?
QPDT Low resistance mux 2:1 Analog switches with enable for 5V
footprint QFN16C_2X2
pins: 1 S2B (io), 2 DB (io), 3 GND (power), 4 DC (io), 5 S2C (io), 6 S1C (io), 7 DD (io), 8 S2D (io), 9 S1D (io), 10 EN# (in), 11 VCC (power), 12 IN (in), 13 S1A (io), 14 S2A (io), 15 DA (io), 16 S1B (io)

## CH440G
designator U?
QPDT Low resistance mux 2:1 Analog switches with enable for 5V
footprint SOP16
footprint TSSOP16
pins: 1 IN (in), 2 S1A (io), 3 S2A (io), 4 DA (io), 5 S1B (io), 6 S2B (io), 7 DB (io), 8 GND (power), 9 DC (io), 10 S2C (io), 11 S1C (io), 12 DD (io), 13 S2D (io), 14 S1D (io), 15 EN# (in), 16 VCC (power)

## CH440P
designator U?
QPDT Low resistance mux 2:1 Analog switches with enable for 5V
footprint QFN16_3X3
pins: 0 GND (power), 1 S2A (io), 2 DA (io), 3 S1B (io), 4 S2B (io), 5 DB (io), 6 GND (power), 7 DC (io), 8 S2C (io), 9 S1C (io), 10 DD (io), 11 S2D (io), 12 S1D (io), 13 EN# (in), 14 VCC (power), 15 IN (in), 16 S1A (io)

## CH442E
designator U?
DPDT Low resistance mux 2:1 Analog switches with enable for 5V
footprint MSOP10
pins: 1 IN (in), 2 S1B (io), 3 S2B (io), 4 DB (io), 5 GND (power), 6 DC (io), 7 S2C (io), 8 S1C (io), 9 EN# (in), 10 VCC (power)

## CH442Q
designator U?
DPDT Low resistance mux 2:1 Analog switches with enable for 5V
footprint QFN10_14X18 (Footprint not found)
pins: 1 DB (io), 2 DC (io), 3 GND (power), 4 S1C (io), 5 S1B (io), 6 S2C (io), 7 S2B (io), 8 EN# (in), 9 VCC (power), 10 IN (in)

## CH443K
designator U?
SPDT Low resistance mux 2:1 Analog switches for 5V
footprint SOT-363
pins: 1 CH1 (io), 2 GND (power), 3 CH0 (io), 4 COM (io), 5 VCC (power), 6 SEL (in)

## CH443L
designator U?
SPDT Low resistance mux 2:1 Analog switches for 5V
footprint DFN6_12X12 (Footprint not found)
pins: 0 GND (power), 1 VCC (power), 2 CH0 (io), 3 CH1 (io), 4 COM (io), 5 SEL (in), 6 GND (power)

## CH444C
designator U?
DPQT Low resistance mux 4:1 Analog switches with enable for 5V
footprint QFN16C_2X2
pins: 1 S1A (io), 2 YA (io), 3 GND (power), 4 YB (io), 5 S1B (io), 6 S2B (io), 7 S3B (io), 8 S4B (io), 9 IN0 (in), 10 NC., 11 VCC (power), 12 EN# (in), 13 IN1 (in), 14 S4A (io), 15 S3A (io), 16 S2A (io)

## CH444G
designator U?
DPQT Low resistance mux 4:1 Analog switches with enable for 5V
footprint SOP16
footprint TSSOP16
pins: 1 EN# (in), 2 IN1 (in), 3 S4A (io), 4 S3A (io), 5 S2A (io), 6 S1A (io), 7 YA (io), 8 GND (power), 9 YB (io), 10 S1B (io), 11 S2B (io), 12 S3B (io), 13 S4B (io), 14 IN0 (in), 15 NC., 16 VCC (power)

## CH444P
designator U?
DPQT Low resistance mux 4:1 Analog switches with enable for 5V
footprint QFN16_3X3
pins: 0 GND (power), 1 S4A (io), 2 S3A (io), 3 S2A (io), 4 S1A (io), 5 YA (io), 6 GND (power), 7 YB (io), 8 S1B (io), 9 S2B (io), 10 S3B (io), 11 S4B (io), 12 IN0 (in), 13 NC., 14 VCC (power), 15 EN# (in), 16 IN1 (in)

## CH445P
designator U?
QPDT Low resistance mux 2:1 Analog switches with enable for 3.3V
footprint QFN16_3X3
pins: 0 GND (power), 1 S2A (io), 2 DA (io), 3 S1B (io), 4 S2B (io), 5 DB (io), 6 GND (power), 7 DC (io), 8 S2C (io), 9 S1C (io), 10 DD (io), 11 S2D (io), 12 S1D (io), 13 EN# (in), 14 VCC (power), 15 IN (in), 16 S1A (io)

## CH446Q
designator U?
8 x 16 Analog switch array, include 128 switches for 12V
footprint LQFP44
pins: 1 X14 (io), 2 X15 (io), 3 X6 (io), 4 X7 (io), 5 X8 (io), 6 X9 (io), 7 X10 (io), 8 X11 (io), 9 NC., 10 P/-S (in), 11 Y7 (io), 12 GND (power), 13 Y6 (io), 14 STB (in), 15 Y5 (io), 16 VEE (power), 17 Y4 (io), 18 AX1 (in), 19 AX2 (in), 20 AY0 (in), 21 AY1 (in), 22 NC., 23 NC., 24 X13 (io), 25 X12 (io), 26 X5 (io), 27 X4 (io), 28 X3 (io), 29 X2 (io), 30 X1 (io), 31 X0 (io), 32 NC., 33 Y0 (io), 34 CS/CK (in), 35 Y1 (io), 36 DAT (in), 37 Y2 (io), 38 VDD (power), 39 Y3 (io), 40 AY2 (in), 41 RST (in), 42 AX3 (in), 43 AX0 (in), 44 NC.

## CH446X
designator U?
5 x 24 Analog switch array, include 120 switches for 12V
footprint LQFP44
pins: 1 X14 (io), 2 X15 (io), 3 X6 (io), 4 X7 (io), 5 X8 (io), 6 X9 (io), 7 X10 (io), 8 X11 (io), 9 NC., 10 NC., 11 X23 (io), 12 GND (power), 13 X22 (io), 14 STB (in), 15 X21 (io), 16 VEE (power), 17 X20 (io), 18 Y1 (io), 19 Y2 (io), 20 Y4 (io), 21 NC., 22 NC., 23 NC., 24 X13 (io), 25 X12 (io), 26 X5 (io), 27 X4 (io), 28 X3 (io), 29 X2 (io), 30 X1 (io), 31 X0 (io), 32 NC., 33 X16 (io), 34 CS/CK (in), 35 X17 (io), 36 DAT (in), 37 X18 (io), 38 VDD (power), 39 X19 (io), 40 NC., 41 RST (in), 42 Y3 (io), 43 Y0 (io), 44 NC.

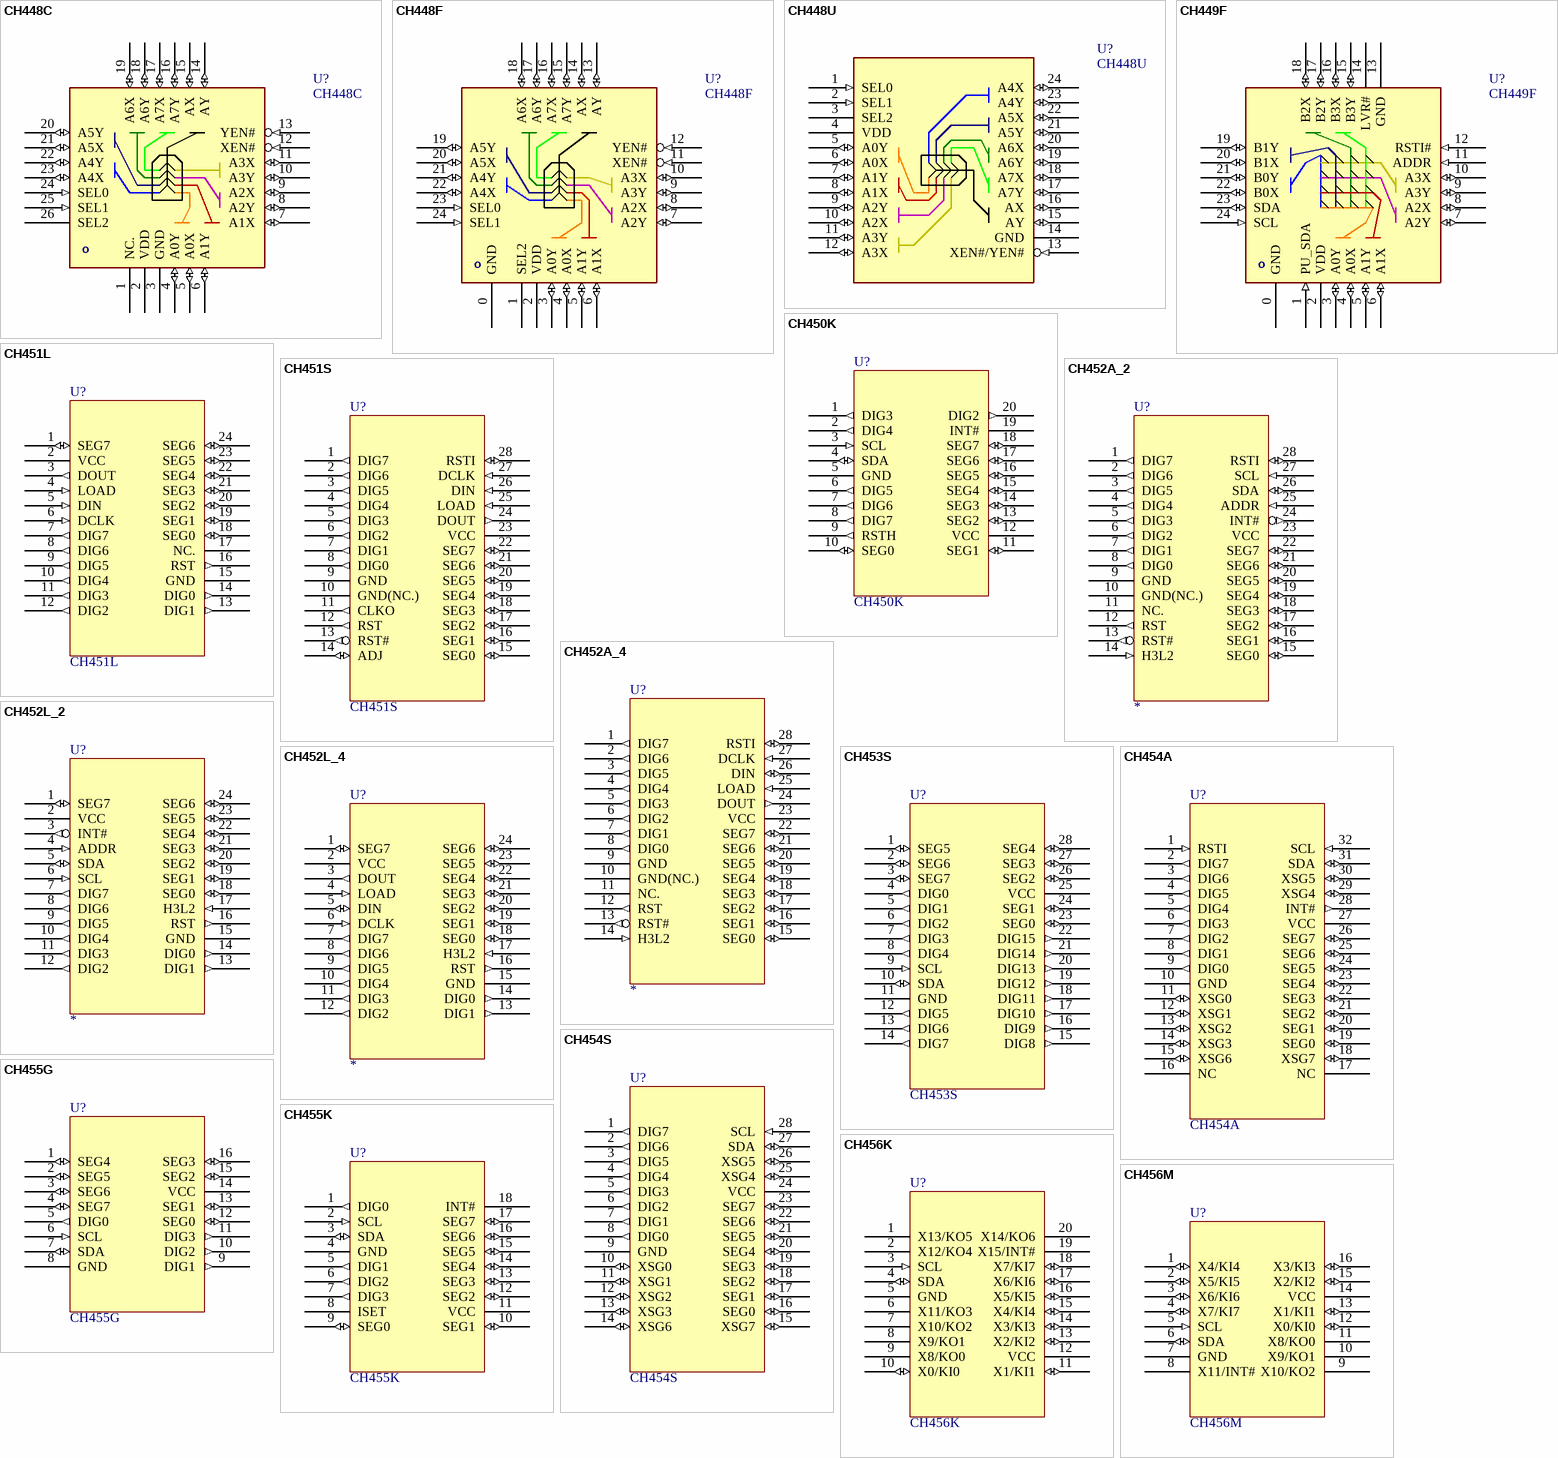
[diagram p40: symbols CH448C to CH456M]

## CH448C
designator U?
USB2.0 mux 8:1 / 16:1 Differential Switch, DPOT with dual enable
footprint QFN26C_3X3
pins: 1 NC., 2 VDD (power), 3 GND (power), 4 A0Y (io), 5 A0X (io), 6 A1Y (io), 7 A1X (io), 8 A2Y (io), 9 A2X (io), 10 A3Y (io), 11 A3X (io), 12 XEN# (in), 13 YEN# (in), 14 AY (io), 15 AX (io), 16 A7Y (io), 17 A7X (io), 18 A6Y (io), 19 A6X (io), 20 A5Y (io), 21 A5X (io), 22 A4Y (io), 23 A4X (io), 24 SEL0 (in), 25 SEL1 (in), 26 SEL2 (power)

## CH448F
designator U?
USB2.0 mux 8:1 / 16:1 Differential Switch, DPOT with dual enable
footprint QFN24_4X4
pins: 0 GND (power), 1 SEL2 (power), 2 VDD (power), 3 A0Y (io), 4 A0X (io), 5 A1Y (io), 6 A1X (io), 7 A2Y (io), 8 A2X (io), 9 A3Y (io), 10 A3X (io), 11 XEN# (in), 12 YEN# (in), 13 AY (io), 14 AX (io), 15 A7Y (io), 16 A7X (io), 17 A6Y (io), 18 A6X (io), 19 A5Y (io), 20 A5X (io), 21 A4Y (io), 22 A4X (io), 23 SEL0 (in), 24 SEL1 (in)

## CH448U
designator U?
USB2.0 mux 8:1 Differential Switch, DPOT with enable
footprint QSOP24 (Footprint not found)
pins: 1 SEL0 (in), 2 SEL1 (in), 3 SEL2 (power), 4 VDD (power), 5 A0Y (io), 6 A0X (io), 7 A1Y (io), 8 A1X (io), 9 A2Y (io), 10 A2X (io), 11 A3Y (io), 12 A3X (io), 13 XEN#/YEN# (in), 14 GND (power), 15 AY (io), 16 AX (io), 17 A7Y (io), 18 A7X (io), 19 A6Y (io), 20 A6X (io), 21 A5Y (io), 22 A5X (io), 23 A4Y (io), 24 A4X (io)

## CH449F
designator U?
USB2.0 4x4 Analog Differential Switch Matrix, QXQX
footprint QFN24_4X4
pins: 0 GND (power), 1 PU_SDA (in), 2 VDD (power), 3 A0Y (io), 4 A0X (io), 5 A1Y (io), 6 A1X (io), 7 A2Y (io), 8 A2X (io), 9 A3Y (io), 10 A3X (io), 11 ADDR (in), 12 RSTI# (in), 13 GND (power), 14 LVR# (oc), 15 B3Y (io), 16 B3X (io), 17 B2Y (io), 18 B2X (io), 19 B1Y (io), 20 B1X (io), 21 B0Y (io), 22 B0X (io), 23 SDA (io), 24 SCL (in)

## CH450K
designator U?
8-Seg * 6 Digits / 48 LEDs Drive & 8x6 Keyboard, I2C/IIC
footprint DIP20
footprint SOP20
pins: 1 DIG3 (out), 2 DIG4 (out), 3 SCL (in), 4 SDA (io), 5 GND (power), 6 DIG5 (out), 7 DIG6 (out), 8 DIG7 (out), 9 RSTH (out), 10 SEG0 (io), 11 SEG1 (io), 12 VCC (power), 13 SEG2 (io), 14 SEG3 (io), 15 SEG4 (io), 16 SEG5 (io), 17 SEG6 (io), 18 SEG7 (io), 19 INT# (oc), 20 DIG2 (out)

## CH451L
designator U?
8-Seg * 8 Digits / 64 LEDs Drive & 8x8 Keyboard, 4 Wire Interface, SPI
footprint DIP24S
pins: 1 SEG7 (io), 2 VCC (power), 3 DOUT (out), 4 LOAD (in), 5 DIN (in), 6 DCLK (in), 7 DIG7 (out), 8 DIG6 (out), 9 DIG5 (out), 10 DIG4 (out), 11 DIG3 (out), 12 DIG2 (out), 13 DIG1 (out), 14 DIG0 (out), 15 GND (power), 16 RST (out), 17 NC., 18 SEG0 (io), 19 SEG1 (io), 20 SEG2 (io), 21 SEG3 (io), 22 SEG4 (io), 23 SEG5 (io), 24 SEG6 (io)

## CH451S
designator U?
8-Seg * 8 Digits / 64 LEDs Drive & 8x8 Keyboard, 4 Wire Interface, SPI
footprint SOP28
footprint DIP28
pins: 1 DIG7 (out), 2 DIG6 (out), 3 DIG5 (out), 4 DIG4 (out), 5 DIG3 (out), 6 DIG2 (out), 7 DIG1 (out), 8 DIG0 (out), 9 GND (power), 10 GND(NC.) (power), 11 CLKO (out), 12 RST (out), 13 RST# (out), 14 ADJ (io), 15 SEG0 (io), 16 SEG1 (io), 17 SEG2 (io), 18 SEG3 (io), 19 SEG4 (io), 20 SEG5 (io), 21 SEG6 (io), 22 SEG7 (io), 23 VCC (power), 24 DOUT (out), 25 LOAD (in), 26 DIN (in), 27 DCLK (in), 28 RSTI (io)

## CH452A_2
designator U?
8-Seg * 8 Digits / 64 LEDs Drive & 8x8 Keyboard, 2 Wire Interface, I2C/IIC
footprint SOP28
footprint DIP28
pins: 1 DIG7 (out), 2 DIG6 (out), 3 DIG5 (out), 4 DIG4 (out), 5 DIG3 (out), 6 DIG2 (out), 7 DIG1 (out), 8 DIG0 (out), 9 GND (power), 10 GND(NC.) (power), 11 NC., 12 RST (out), 13 RST# (out), 14 H3L2 (in), 15 SEG0 (io), 16 SEG1 (io), 17 SEG2 (io), 18 SEG3 (io), 19 SEG4 (io), 20 SEG5 (io), 21 SEG6 (io), 22 SEG7 (io), 23 VCC (power), 24 INT# (out), 25 ADDR (in), 26 SDA (io), 27 SCL (in), 28 RSTI (io)

## CH452A_4
designator U?
8-Seg * 8 Digits / 64 LEDs Drive & 8x8 Keyboard, 4 Wire Interface, SPI
footprint SOP28
footprint DIP28
pins: 1 DIG7 (out), 2 DIG6 (out), 3 DIG5 (out), 4 DIG4 (out), 5 DIG3 (out), 6 DIG2 (out), 7 DIG1 (out), 8 DIG0 (out), 9 GND (power), 10 GND(NC.) (power), 11 NC., 12 RST (out), 13 RST# (out), 14 H3L2 (in), 15 SEG0 (io), 16 SEG1 (io), 17 SEG2 (io), 18 SEG3 (io), 19 SEG4 (io), 20 SEG5 (io), 21 SEG6 (io), 22 SEG7 (io), 23 VCC (power), 24 DOUT (out), 25 LOAD (in), 26 DIN (io), 27 DCLK (in), 28 RSTI (io)

## CH452L_2
designator U?
8-Seg * 8 Digits / 64 LEDs Drive & 8x8 Keyboard, 2 Wire Interface, I2C/IIC
footprint DIP24S
pins: 1 SEG7 (io), 2 VCC (power), 3 INT# (out), 4 ADDR (in), 5 SDA (io), 6 SCL (in), 7 DIG7 (out), 8 DIG6 (out), 9 DIG5 (out), 10 DIG4 (out), 11 DIG3 (out), 12 DIG2 (out), 13 DIG1 (out), 14 DIG0 (out), 15 GND (power), 16 RST (out), 17 H3L2 (in), 18 SEG0 (io), 19 SEG1 (io), 20 SEG2 (io), 21 SEG3 (io), 22 SEG4 (io), 23 SEG5 (io), 24 SEG6 (io)

## CH452L_4
designator U?
8-Seg * 8 Digits / 64 LEDs Drive & 8x8 Keyboard, 4 Wire Interface, SPI
footprint DIP24S
pins: 1 SEG7 (io), 2 VCC (power), 3 DOUT (out), 4 LOAD (in), 5 DIN (io), 6 DCLK (in), 7 DIG7 (out), 8 DIG6 (out), 9 DIG5 (out), 10 DIG4 (out), 11 DIG3 (out), 12 DIG2 (out), 13 DIG1 (out), 14 DIG0 (out), 15 GND (power), 16 RST (out), 17 H3L2 (in), 18 SEG0 (io), 19 SEG1 (io), 20 SEG2 (io), 21 SEG3 (io), 22 SEG4 (io), 23 SEG5 (io), 24 SEG6 (io)

## CH453S
designator U?
8-Seg * 16 Digits / 128 LEDs Drive, I2C/IIC
footprint SOP28
footprint DIP28S
pins: 1 SEG5 (io), 2 SEG6 (io), 3 SEG7 (io), 4 DIG0 (out), 5 DIG1 (out), 6 DIG2 (out), 7 DIG3 (out), 8 DIG4 (out), 9 SCL (in), 10 SDA (io), 11 GND (power), 12 DIG5 (out), 13 DIG6 (out), 14 DIG7 (out), 15 DIG8 (out), 16 DIG9 (out), 17 DIG10 (out), 18 DIG11 (out), 19 DIG12 (out), 20 DIG13 (out), 21 DIG14 (out), 22 DIG15 (out), 23 SEG0 (io), 24 SEG1 (io), 25 VCC (power), 26 SEG2 (io), 27 SEG3 (io), 28 SEG4 (io)

## CH454A
designator U?
16 Segments * 8 Digits / 128 LEDs Drive & 8x8 Keyboard, I2C/IIC
footprint SDIP32
pins: 1 RSTI (in), 2 DIG7 (out), 3 DIG6 (out), 4 DIG5 (out), 5 DIG4 (out), 6 DIG3 (out), 7 DIG2 (out), 8 DIG1 (out), 9 DIG0 (out), 10 GND (power), 11 XSG0 (io), 12 XSG1 (io), 13 XSG2 (io), 14 XSG3 (io), 15 XSG6 (io), 16 NC, 17 NC, 18 XSG7 (io), 19 SEG0 (io), 20 SEG1 (io), 21 SEG2 (io), 22 SEG3 (io), 23 SEG4 (io), 24 SEG5 (io), 25 SEG6 (io), 26 SEG7 (io), 27 VCC (power), 28 INT# (out), 29 XSG4 (io), 30 XSG5 (io), 31 SDA (io), 32 SCL (in)

## CH454S
designator U?
16 Segments * 8 Digits / 128 LEDs Drive & 8x8 Keyboard, I2C/IIC
footprint SOP28
pins: 1 DIG7 (out), 2 DIG6 (out), 3 DIG5 (out), 4 DIG4 (out), 5 DIG3 (out), 6 DIG2 (out), 7 DIG1 (out), 8 DIG0 (out), 9 GND (power), 10 XSG0 (io), 11 XSG1 (io), 12 XSG2 (io), 13 XSG3 (io), 14 XSG6 (io), 15 XSG7 (io), 16 SEG0 (io), 17 SEG1 (io), 18 SEG2 (io), 19 SEG3 (io), 20 SEG4 (io), 21 SEG5 (io), 22 SEG6 (io), 23 SEG7 (io), 24 VCC (power), 25 XSG4 (io), 26 XSG5 (io), 27 SDA (io), 28 SCL (in)

## CH455G
designator U?
8-Seg * 4 Digits / 32 LEDs Drive & 7x4 Keyboard, I2C/IIC
footprint SOP16
pins: 1 SEG4 (io), 2 SEG5 (io), 3 SEG6 (io), 4 SEG7 (io), 5 DIG0 (out), 6 SCL (in), 7 SDA (io), 8 GND (power), 9 DIG1 (out), 10 DIG2 (out), 11 DIG3 (out), 12 SEG0 (io), 13 SEG1 (io), 14 VCC (power), 15 SEG2 (io), 16 SEG3 (io)

## CH455K
designator U?
8-Seg * 4 Digits / 32 LEDs Drive & 7x4 Keyboard, I2C/IIC
footprint SOP18
footprint DIP18
pins: 1 DIG0 (out), 2 SCL (in), 3 SDA (io), 4 GND (power), 5 DIG1 (out), 6 DIG2 (out), 7 DIG3 (out), 8 ISET, 9 SEG0 (io), 10 SEG1 (io), 11 VCC (power), 12 SEG2 (io), 13 SEG3 (io), 14 SEG4 (io), 15 SEG5 (io), 16 SEG6 (io), 17 SEG7 (io), 18 INT# (oc)

## CH456K
designator U?
8-Seg * 16 Digits / 128 LEDs Drive & 8x8 Keyboard, I2C/IIC
footprint DIP20
footprint SOP20
pins: 1 X13/KO5 (hiz), 2 X12/KO4 (hiz), 3 SCL (in), 4 SDA (io), 5 GND (power), 6 X11/KO3 (hiz), 7 X10/KO2 (hiz), 8 X9/KO1 (hiz), 9 X8/KO0 (hiz), 10 X0/KI0 (io), 11 X1/KI1 (io), 12 VCC (power), 13 X2/KI2 (io), 14 X3/KI3 (io), 15 X4/KI4 (io), 16 X5/KI5 (io), 17 X6/KI6 (io), 18 X7/KI7 (io), 19 X15/INT# (hiz), 20 X14/KO6 (hiz)

## CH456M
designator U?
8-Seg * 12 Digits / 96 LEDs Drive & 4x8 Keyboard, I2C/IIC
footprint DIP16
footprint SOP16
pins: 1 X4/KI4 (io), 2 X5/KI5 (io), 3 X6/KI6 (io), 4 X7/KI7 (io), 5 SCL (in), 6 SDA (io), 7 GND (power), 8 X11/INT# (hiz), 9 X10/KO2 (hiz), 10 X9/KO1 (hiz), 11 X8/KO0 (hiz), 12 X0/KI0 (io), 13 X1/KI1 (io), 14 VCC (power), 15 X2/KI2 (io), 16 X3/KI3 (io)

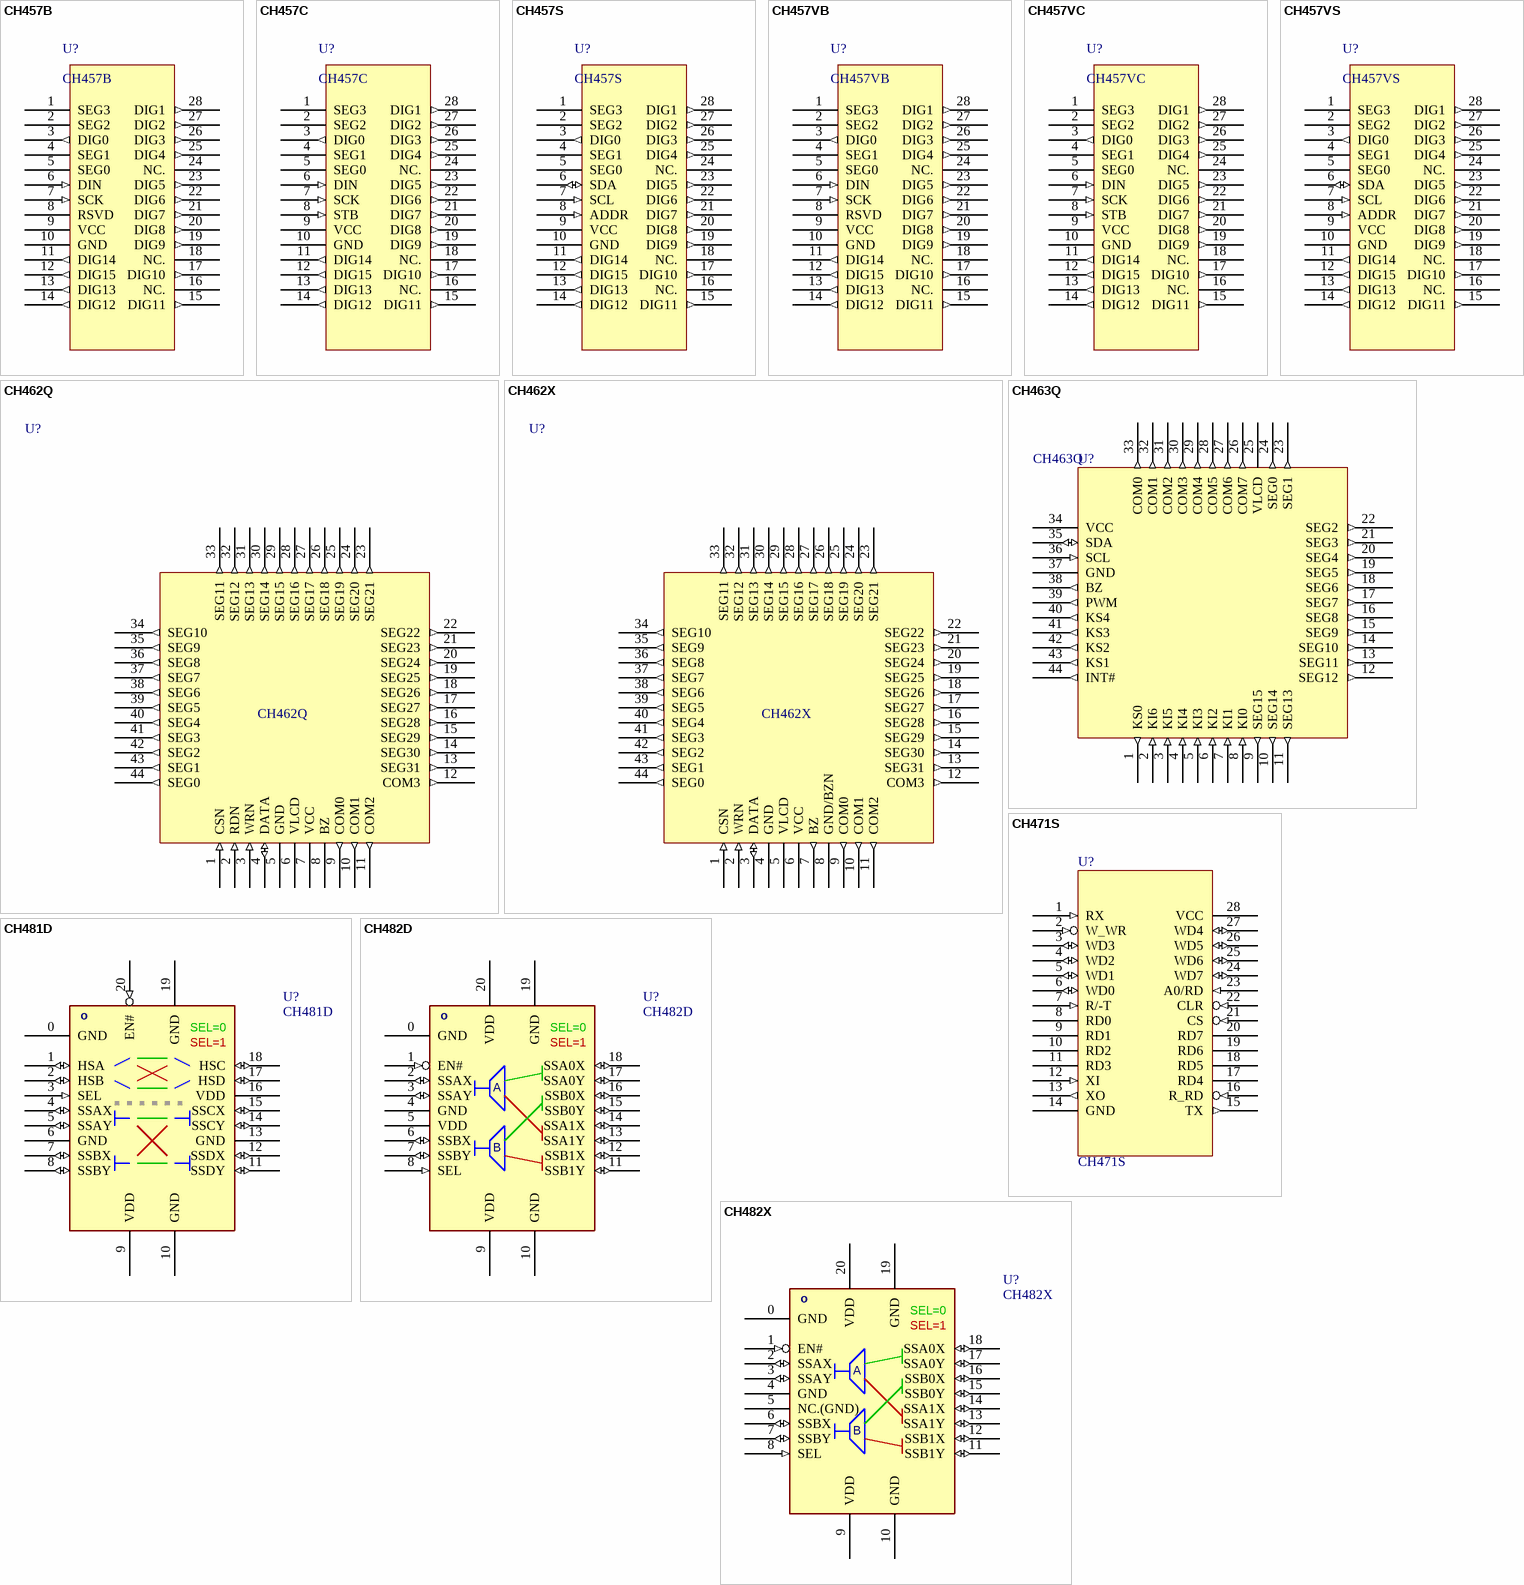
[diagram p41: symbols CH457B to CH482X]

## CH457B
designator U?
8-Seg * 16 Digits / 128 LEDs Drive, I2C/IIC/2-wire/3-wire/VCC@5V
footprint SOP28
pins: 1 SEG3 (hiz), 2 SEG2 (hiz), 3 DIG0 (out), 4 SEG1 (hiz), 5 SEG0 (hiz), 6 DIN (in), 7 SCK (in), 8 RSVD, 9 VCC (power), 10 GND (power), 11 DIG14 (out), 12 DIG15 (out), 13 DIG13 (out), 14 DIG12 (out), 15 DIG11 (out), 16 NC., 17 DIG10 (out), 18 NC., 19 DIG9 (out), 20 DIG8 (out), 21 DIG7 (out), 22 DIG6 (out), 23 DIG5 (out), 24 NC., 25 DIG4 (out), 26 DIG3 (out), 27 DIG2 (out), 28 DIG1 (out)

## CH457C
designator U?
8-Seg * 16 Digits / 128 LEDs Drive, I2C/IIC/2-wire/3-wire/VCC@5V
footprint SOP28
pins: 1 SEG3 (hiz), 2 SEG2 (hiz), 3 DIG0 (out), 4 SEG1 (hiz), 5 SEG0 (hiz), 6 DIN (in), 7 SCK (in), 8 STB (in), 9 VCC (power), 10 GND (power), 11 DIG14 (out), 12 DIG15 (out), 13 DIG13 (out), 14 DIG12 (out), 15 DIG11 (out), 16 NC., 17 DIG10 (out), 18 NC., 19 DIG9 (out), 20 DIG8 (out), 21 DIG7 (out), 22 DIG6 (out), 23 DIG5 (out), 24 NC., 25 DIG4 (out), 26 DIG3 (out), 27 DIG2 (out), 28 DIG1 (out)

## CH457S
designator U?
8-Seg * 16 Digits / 128 LEDs Drive, I2C/IIC/2-wire/3-wire/VCC@5V
footprint SOP28
pins: 1 SEG3 (hiz), 2 SEG2 (hiz), 3 DIG0 (out), 4 SEG1 (hiz), 5 SEG0 (hiz), 6 SDA (io), 7 SCL (in), 8 ADDR (in), 9 VCC (power), 10 GND (power), 11 DIG14 (out), 12 DIG15 (out), 13 DIG13 (out), 14 DIG12 (out), 15 DIG11 (out), 16 NC., 17 DIG10 (out), 18 NC., 19 DIG9 (out), 20 DIG8 (out), 21 DIG7 (out), 22 DIG6 (out), 23 DIG5 (out), 24 NC., 25 DIG4 (out), 26 DIG3 (out), 27 DIG2 (out), 28 DIG1 (out)

## CH457VB
designator U?
8-Seg * 16 Digits / 128 LEDs Drive, I2C/IIC/2-wire/3-wire/VCC@3.3V
footprint SOP28
pins: 1 SEG3 (hiz), 2 SEG2 (hiz), 3 DIG0 (out), 4 SEG1 (hiz), 5 SEG0 (hiz), 6 DIN (in), 7 SCK (in), 8 RSVD, 9 VCC (power), 10 GND (power), 11 DIG14 (out), 12 DIG15 (out), 13 DIG13 (out), 14 DIG12 (out), 15 DIG11 (out), 16 NC., 17 DIG10 (out), 18 NC., 19 DIG9 (out), 20 DIG8 (out), 21 DIG7 (out), 22 DIG6 (out), 23 DIG5 (out), 24 NC., 25 DIG4 (out), 26 DIG3 (out), 27 DIG2 (out), 28 DIG1 (out)

## CH457VC
designator U?
8-Seg * 16 Digits / 128 LEDs Drive, I2C/IIC/2-wire/3-wire/VCC@3.3V
footprint SOP28
pins: 1 SEG3 (hiz), 2 SEG2 (hiz), 3 DIG0 (out), 4 SEG1 (hiz), 5 SEG0 (hiz), 6 DIN (in), 7 SCK (in), 8 STB (in), 9 VCC (power), 10 GND (power), 11 DIG14 (out), 12 DIG15 (out), 13 DIG13 (out), 14 DIG12 (out), 15 DIG11 (out), 16 NC., 17 DIG10 (out), 18 NC., 19 DIG9 (out), 20 DIG8 (out), 21 DIG7 (out), 22 DIG6 (out), 23 DIG5 (out), 24 NC., 25 DIG4 (out), 26 DIG3 (out), 27 DIG2 (out), 28 DIG1 (out)

## CH457VS
designator U?
8-Seg * 16 Digits / 128 LEDs Drive, I2C/IIC/2-wire/3-wire/VCC@3.3V
footprint SOP28
pins: 1 SEG3 (hiz), 2 SEG2 (hiz), 3 DIG0 (out), 4 SEG1 (hiz), 5 SEG0 (hiz), 6 SDA (io), 7 SCL (in), 8 ADDR (in), 9 VCC (power), 10 GND (power), 11 DIG14 (out), 12 DIG15 (out), 13 DIG13 (out), 14 DIG12 (out), 15 DIG11 (out), 16 NC., 17 DIG10 (out), 18 NC., 19 DIG9 (out), 20 DIG8 (out), 21 DIG7 (out), 22 DIG6 (out), 23 DIG5 (out), 24 NC., 25 DIG4 (out), 26 DIG3 (out), 27 DIG2 (out), 28 DIG1 (out)

## CH462Q
designator U?
32*4 LCD controller, 4-wire
footprint LQFP44
pins: 1 CSN (in), 2 RDN (in), 3 WRN (in), 4 DATA (io), 5 GND (power), 6 VLCD (power), 7 VCC (power), 8 BZ, 9 COM0 (out), 10 COM1 (out), 11 COM2 (out), 12 COM3 (out), 13 SEG31 (out), 14 SEG30 (out), 15 SEG29 (out), 16 SEG28 (out), 17 SEG27 (out), 18 SEG26 (out), 19 SEG25 (out), 20 SEG24 (out), 21 SEG23 (out), 22 SEG22 (out), 23 SEG21 (out), 24 SEG20 (out), 25 SEG19 (out), 26 SEG18 (out), 27 SEG17 (out), 28 SEG16 (out), 29 SEG15 (out), 30 SEG14 (out), 31 SEG13 (out), 32 SEG12 (out), 33 SEG11 (out), 34 SEG10 (out), 35 SEG9 (out), 36 SEG8 (out), 37 SEG7 (out), 38 SEG6 (out), 39 SEG5 (out), 40 SEG4 (out), 41 SEG3 (out), 42 SEG2 (out), 43 SEG1 (out), 44 SEG0 (out)

## CH462X
designator U?
32*4 LCD controller, 3-wire
footprint LQFP44
pins: 1 CSN (in), 2 WRN (in), 3 DATA (io), 4 GND (power), 5 VLCD (power), 6 VCC (power), 7 BZ (out), 8 GND/BZN (power), 9 COM0 (out), 10 COM1 (out), 11 COM2 (out), 12 COM3 (out), 13 SEG31 (out), 14 SEG30 (out), 15 SEG29 (out), 16 SEG28 (out), 17 SEG27 (out), 18 SEG26 (out), 19 SEG25 (out), 20 SEG24 (out), 21 SEG23 (out), 22 SEG22 (out), 23 SEG21 (out), 24 SEG20 (out), 25 SEG19 (out), 26 SEG18 (out), 27 SEG17 (out), 28 SEG16 (out), 29 SEG15 (out), 30 SEG14 (out), 31 SEG13 (out), 32 SEG12 (out), 33 SEG11 (out), 34 SEG10 (out), 35 SEG9 (out), 36 SEG8 (out), 37 SEG7 (out), 38 SEG6 (out), 39 SEG5 (out), 40 SEG4 (out), 41 SEG3 (out), 42 SEG2 (out), 43 SEG1 (out), 44 SEG0 (out)

## CH463Q
designator U?
16*8 LCD controller & 7*5 keyboard, 2-wire
footprint LQFP44
pins: 1 KS0 (out), 2 KI6 (in), 3 KI5 (in), 4 KI4 (in), 5 KI3 (in), 6 KI2 (in), 7 KI1 (in), 8 KI0 (in), 9 SEG15 (out), 10 SEG14 (out), 11 SEG13 (out), 12 SEG12 (out), 13 SEG11 (out), 14 SEG10 (out), 15 SEG9 (out), 16 SEG8 (out), 17 SEG7 (out), 18 SEG6 (out), 19 SEG5 (out), 20 SEG4 (out), 21 SEG3 (out), 22 SEG2 (out), 23 SEG1 (out), 24 SEG0 (out), 25 VLCD (power), 26 COM7 (out), 27 COM6 (out), 28 COM5 (out), 29 COM4 (out), 30 COM3 (out), 31 COM2 (out), 32 COM1 (out), 33 COM0 (out), 34 VCC (power), 35 SDA (io), 36 SCL (in), 37 GND (power), 38 BZ (out), 39 PWM (out), 40 KS4 (out), 41 KS3 (out), 42 KS2 (out), 43 KS1 (out), 44 INT# (out)

## CH471S
designator U?
footprint SOP28
pins: 1 RX (in), 2 W_WR (in), 3 WD3 (io), 4 WD2 (io), 5 WD1 (io), 6 WD0 (io), 7 R/-T (in), 8 RD0 (hiz), 9 RD1 (hiz), 10 RD2 (hiz), 11 RD3 (hiz), 12 XI (in), 13 XO (out), 14 GND (power), 15 TX (out), 16 R_RD (in), 17 RD4 (hiz), 18 RD5 (hiz), 19 RD6 (hiz), 20 RD7 (hiz), 21 CS (in), 22 CLR (in), 23 A0/RD (in), 24 WD7 (io), 25 WD6 (io), 26 WD5 (io), 27 WD4 (io), 28 VCC (power)

## CH481D
designator U?
DP/PCIe/SATA/USB3.0 Differential Switch, QPDT
footprint QFN20_2.5X4.5
pins: 0 GND (power), 1 HSA (io), 2 HSB (io), 3 SEL (in), 4 SSAX (io), 5 SSAY (io), 6 GND (power), 7 SSBX (io), 8 SSBY (io), 9 VDD (power), 10 GND (power), 11 SSDY (io), 12 SSDX (io), 13 GND (power), 14 SSCY (io), 15 SSCX (io), 16 VDD (power), 17 HSD (io), 18 HSC (io), 19 GND (power), 20 EN# (in)

## CH482D
designator U?
DP/PCIe/SATA/USB3.0 Differential Switch, QPDT
footprint QFN20_2.5X4.5
pins: 0 GND (power), 1 EN# (in), 2 SSAX (io), 3 SSAY (io), 4 GND (power), 5 VDD (power), 6 SSBX (io), 7 SSBY (io), 8 SEL (in), 9 VDD (power), 10 GND (power), 11 SSB1Y (io), 12 SSB1X (io), 13 SSA1Y (io), 14 SSA1X (io), 15 SSB0Y (io), 16 SSB0X (io), 17 SSA0Y (io), 18 SSA0X (io), 19 GND (power), 20 VDD (power)

## CH482X
designator U?
DP/PCIe/SATA/USB3.0/USB3.2 Differential Switch, QPDT
footprint QFN20_2.5X4.5
pins: 0 GND (power), 1 EN# (in), 2 SSAX (io), 3 SSAY (io), 4 GND (power), 5 NC.(GND), 6 SSBX (io), 7 SSBY (io), 8 SEL (in), 9 VDD (power), 10 GND (power), 11 SSB1Y (io), 12 SSB1X (io), 13 SSA1Y (io), 14 SSA1X (io), 15 SSB0Y (io), 16 SSB0X (io), 17 SSA0Y (io), 18 SSA0X (io), 19 GND (power), 20 VDD (power)

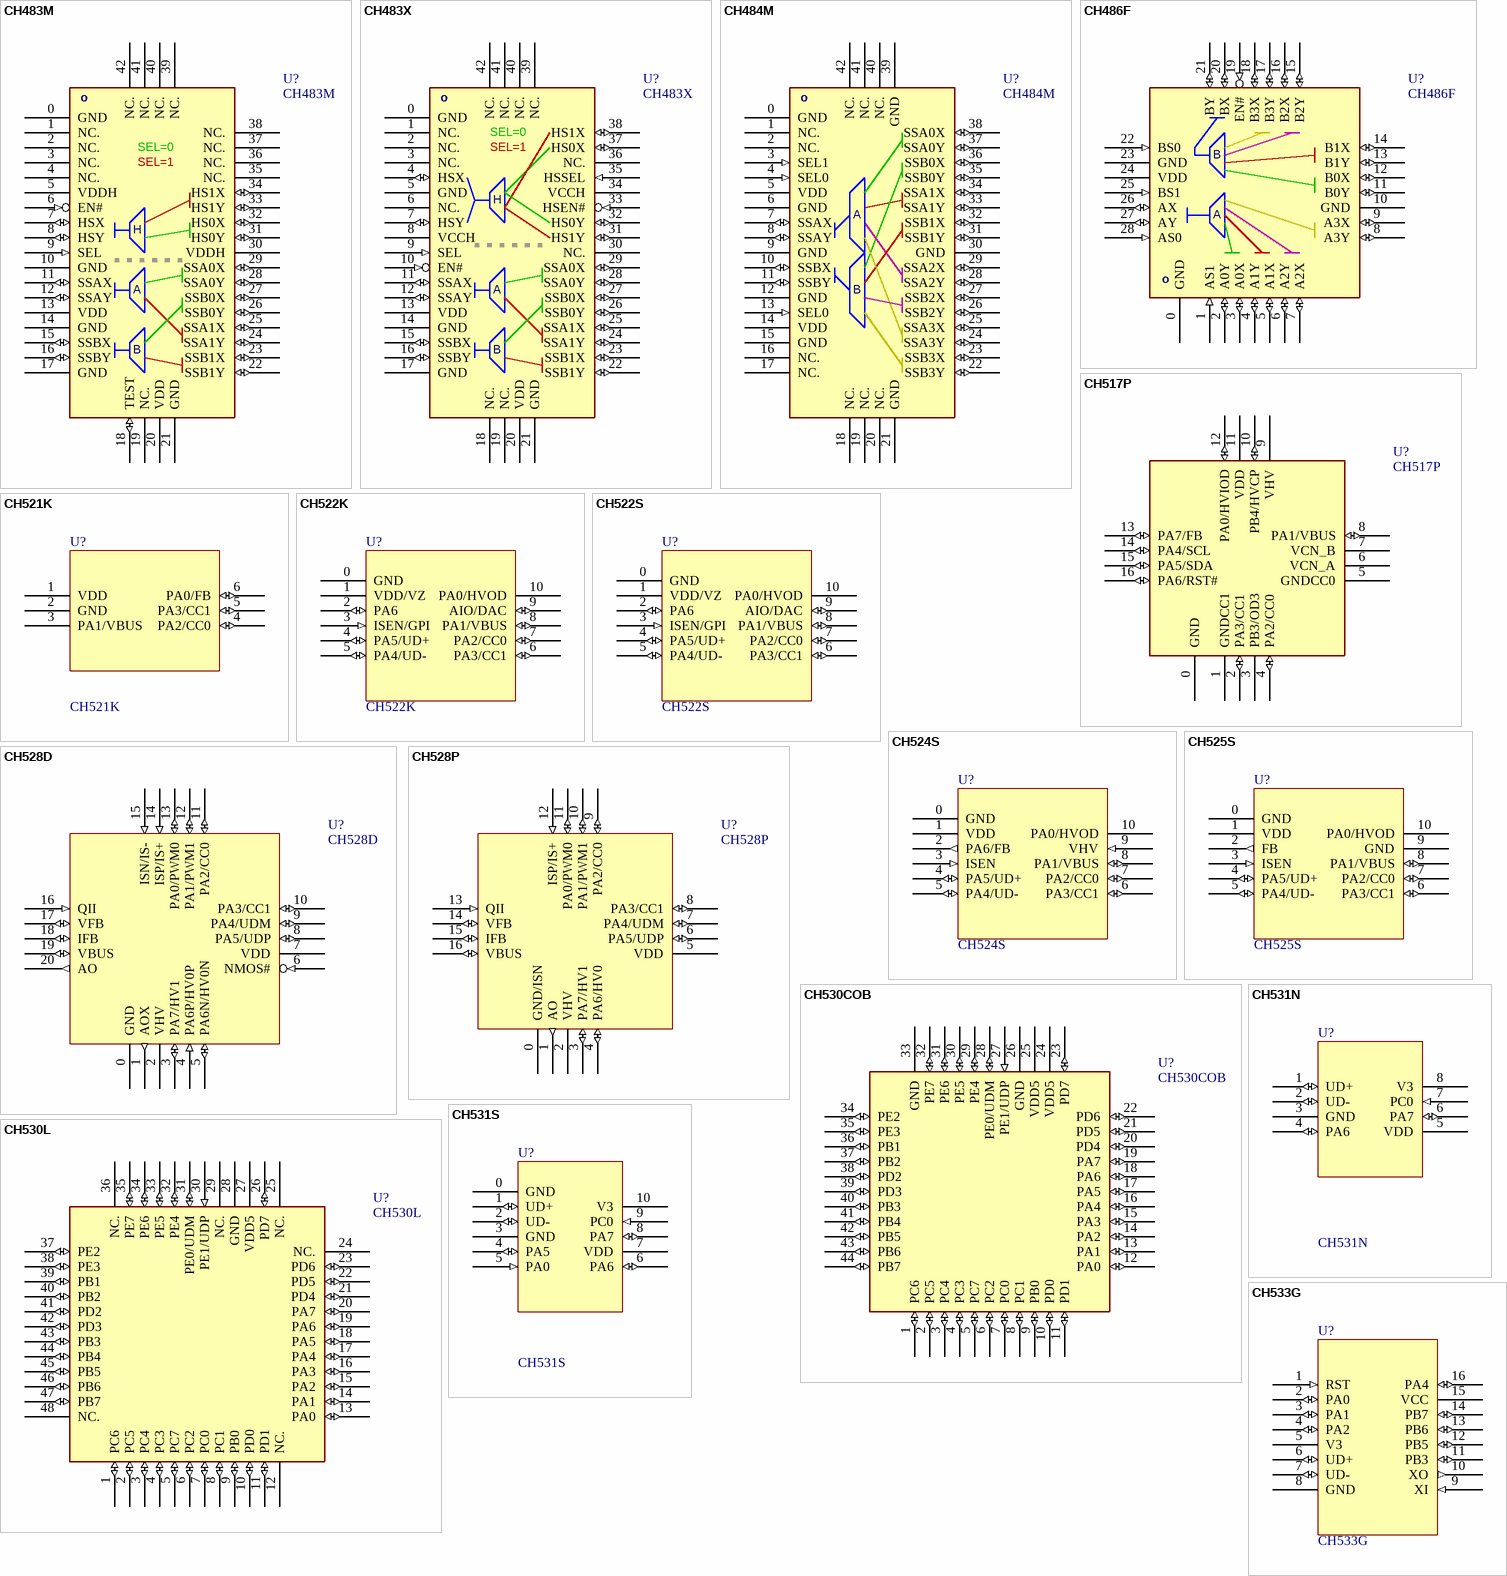
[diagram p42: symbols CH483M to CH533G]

## CH483M
designator U?
DP/PCIe/SATA/USB3.0 & USB2.0 Differential Switch, QPDT+DPDT
footprint QFN42_3.5X9
pins: 0 GND (power), 1 NC., 2 NC., 3 NC., 4 NC., 5 VDDH (power), 6 EN# (in), 7 HSX (io), 8 HSY (io), 9 SEL (in), 10 GND (power), 11 SSAX (io), 12 SSAY (io), 13 VDD (power), 14 GND (power), 15 SSBX (io), 16 SSBY (io), 17 GND (power), 18 TEST (io), 19 NC., 20 VDD (power), 21 GND (power), 22 SSB1Y (io), 23 SSB1X (io), 24 SSA1Y (io), 25 SSA1X (io), 26 SSB0Y (io), 27 SSB0X (io), 28 SSA0Y (io), 29 SSA0X (io), 30 VDDH (power), 31 HS0Y (io), 32 HS0X (io), 33 HS1Y (io), 34 HS1X (io), 35 NC., 36 NC., 37 NC., 38 NC., 39 NC., 40 NC., 41 NC., 42 NC.

## CH483X
designator U?
DP/PCIe/SATA/USB3.0 & USB2.0 Differential Switch, QPDT+DPDT
footprint QFN42_3.5X9
pins: 0 GND (power), 1 NC., 2 NC., 3 NC., 4 HSX (io), 5 GND (power), 6 NC., 7 HSY (io), 8 VCCH (power), 9 SEL (in), 10 EN# (in), 11 SSAX (io), 12 SSAY (io), 13 VDD (power), 14 GND (power), 15 SSBX (io), 16 SSBY (io), 17 GND (power), 18 NC., 19 NC., 20 VDD (power), 21 GND (power), 22 SSB1Y (io), 23 SSB1X (io), 24 SSA1Y (io), 25 SSA1X (io), 26 SSB0Y (io), 27 SSB0X (io), 28 SSA0Y (io), 29 SSA0X (io), 30 NC., 31 HS1Y (io), 32 HS0Y (io), 33 HSEN# (in), 34 VCCH (power), 35 HSSEL (in), 36 NC., 37 HS0X (io), 38 HS1X (io), 39 NC., 40 NC., 41 NC., 42 NC.

## CH484M
designator U?
DP/PCIe/SATA/USB3.0 Differential Switch, QPQT
footprint QFN42_3.5X9
pins: 0 GND (power), 1 NC., 2 NC., 3 SEL1 (in), 4 SEL0 (in), 5 VDD (power), 6 GND (power), 7 SSAX (io), 8 SSAY (io), 9 GND (power), 10 SSBX (io), 11 SSBY (io), 12 GND (power), 13 SEL0 (in), 14 VDD (power), 15 GND (power), 16 NC., 17 NC., 18 NC., 19 NC., 20 NC., 21 GND (power), 22 SSB3Y (io), 23 SSB3X (io), 24 SSA3Y (io), 25 SSA3X (io), 26 SSB2Y (io), 27 SSB2X (io), 28 SSA2Y (io), 29 SSA2X (io), 30 GND (power), 31 SSB1Y (io), 32 SSB1X (io), 33 SSA1Y (io), 34 SSA1X (io), 35 SSB0Y (io), 36 SSB0X (io), 37 SSA0Y (io), 38 SSA0X (io), 39 GND (power), 40 NC., 41 NC., 42 NC.

## CH486F
designator U?
USB2.0/1.5Gbps dual mux 4:1 Differential Switch, QPQT
footprint QFN28_4X4
pins: 0 GND (power), 1 AS1 (in), 2 A0Y (io), 3 A0X (io), 4 A1Y (io), 5 A1X (io), 6 A2Y (io), 7 A2X (io), 8 A3Y (io), 9 A3X (io), 10 GND (power), 11 B0Y (io), 12 B0X (io), 13 B1Y (io), 14 B1X (io), 15 B2Y (io), 16 B2X (io), 17 B3Y (io), 18 B3X (io), 19 EN# (in), 20 BX (io), 21 BY (io), 22 BS0 (in), 23 GND (power), 24 VDD (power), 25 BS1 (in), 26 AX (io), 27 AY (io), 28 AS0 (in)

## CH517P
designator U?
8 bit RISC MCU with USB PD & type-C power manager
footprint QFN16_3X3
pins: 0 GND (power), 1 GNDCC1 (power), 2 PA3/CC1 (io), 3 PB3/OD3 (oc), 4 PA2/CC0 (io), 5 GNDCC0 (power), 6 VCN_A (power), 7 VCN_B (power), 8 PA1/VBUS (io), 9 VHV (power), 10 PB4/HVCP (io), 11 VDD (power), 12 PA0/HVIOD (io), 13 PA7/FB (io), 14 PA4/SCL (io), 15 PA5/SDA (io), 16 PA6/RST# (io)

## CH521K
designator U?
8 bit RISC MCU with USB PD & type-C power manager
footprint SOT-23-6
pins: 1 VDD (power), 2 GND (power), 3 PA1/VBUS (oc), 4 PA2/CC0 (io), 5 PA3/CC1 (io), 6 PA0/FB (io)

## CH522K
designator U?
8 bit RISC MCU with USB PD & type-C power consumer
footprint ESSOP10
pins: 0 GND (power), 1 VDD/VZ (power), 2 PA6 (io), 3 ISEN/GPI (in), 4 PA5/UD+ (io), 5 PA4/UD- (io), 6 PA3/CC1 (io), 7 PA2/CC0 (io), 8 PA1/VBUS (io), 9 AIO/DAC (io), 10 PA0/HVOD (oc)

## CH522S
designator U?
8 bit RISC MCU with USB PD & type-C power module
footprint ESSOP10
pins: 0 GND (power), 1 VDD/VZ (power), 2 PA6 (io), 3 ISEN/GPI (in), 4 PA5/UD+ (io), 5 PA4/UD- (io), 6 PA3/CC1 (io), 7 PA2/CC0 (io), 8 PA1/VBUS (io), 9 AIO/DAC (io), 10 PA0/HVOD (oc)

## CH524S
designator U?
8 bit RISC MCU with USB PD & type-C power manager
footprint ESSOP10
pins: 0 GND (power), 1 VDD (power), 2 PA6/FB (out), 3 ISEN (in), 4 PA5/UD+ (io), 5 PA4/UD- (io), 6 PA3/CC1 (io), 7 PA2/CC0 (io), 8 PA1/VBUS (io), 9 VHV (in), 10 PA0/HVOD (oc)

## CH525S
designator U?
8 bit RISC MCU with USB PD & type-C power manager
footprint ESSOP10
pins: 0 GND (power), 1 VDD (power), 2 FB (out), 3 ISEN (in), 4 PA5/UD+ (io), 5 PA4/UD- (io), 6 PA3/CC1 (io), 7 PA2/CC0 (io), 8 PA1/VBUS (io), 9 GND (power), 10 PA0/HVOD (oc)

## CH528D
designator U?
8 bit RISC MCU with USB PD & type-C & QI high voltage power manager
footprint QFN20_3X3
pins: 0 GND (power), 1 AOX (out), 2 VHV (power), 3 PA7/HV1 (io), 4 PA6P/HV0P (in), 5 PA6N/HV0N (io), 6 NMOS# (in), 7 VDD (power), 8 PA5/UDP (io), 9 PA4/UDM (io), 10 PA3/CC1 (io), 11 PA2/CC0 (io), 12 PA1/PWM1 (io), 13 PA0/PWM0 (io), 14 ISP/IS+ (in), 15 ISN/IS- (in), 16 QII (in), 17 VFB (io), 18 IFB (io), 19 VBUS (io), 20 AO (out)

## CH528P
designator U?
8 bit RISC MCU with USB PD & type-C & QI high voltage power manager
footprint QFN16_3X3
pins: 0 GND/ISN (power), 1 AO (out), 2 VHV (power), 3 PA7/HV1 (io), 4 PA6/HV0 (io), 5 VDD (power), 6 PA5/UDP (io), 7 PA4/UDM (io), 8 PA3/CC1 (io), 9 PA2/CC0 (io), 10 PA1/PWM1 (io), 11 PA0/PWM0 (io), 12 ISP/IS+ (in), 13 QII (in), 14 VFB (io), 15 IFB (io), 16 VBUS (io)

## CH530COB
designator U?
8 bit RISC MCU with low-speed USB
footprint DIE
pins: 1 PC6 (io), 2 PC5 (io), 3 PC4 (io), 4 PC3 (io), 5 PC7 (io), 6 PC2 (io), 7 PC0 (io), 8 PC1 (io), 9 PB0 (io), 10 PD0 (io), 11 PD1 (io), 12 PA0 (io), 13 PA1 (io), 14 PA2 (io), 15 PA3 (io), 16 PA4 (io), 17 PA5 (io), 18 PA6 (io), 19 PA7 (io), 20 PD4 (io), 21 PD5 (io), 22 PD6 (io), 23 PD7 (io), 24 VDD5 (power), 25 VDD5 (power), 26 GND (power), 27 PE1/UDP (in), 28 PE0/UDM (io), 29 PE4 (io), 30 PE5 (io), 31 PE6 (io), 32 PE7 (io), 33 GND (power), 34 PE2 (io), 35 PE3 (io), 36 PB1 (io), 37 PB2 (io), 38 PD2 (io), 39 PD3 (io), 40 PB3 (io), 41 PB4 (io), 42 PB5 (io), 43 PB6 (io), 44 PB7 (io)

## CH530L
designator U?
8 bit RISC MCU with low-speed USB
footprint LQFP48
pins: 1 PC6 (io), 2 PC5 (io), 3 PC4 (io), 4 PC3 (io), 5 PC7 (io), 6 PC2 (io), 7 PC0 (io), 8 PC1 (io), 9 PB0 (io), 10 PD0 (io), 11 PD1 (io), 12 NC., 13 PA0 (io), 14 PA1 (io), 15 PA2 (io), 16 PA3 (io), 17 PA4 (io), 18 PA5 (io), 19 PA6 (io), 20 PA7 (io), 21 PD4 (io), 22 PD5 (io), 23 PD6 (io), 24 NC., 25 NC., 26 PD7 (io), 27 VDD5 (power), 28 GND (power), 29 NC., 30 PE1/UDP (in), 31 PE0/UDM (io), 32 PE4 (io), 33 PE5 (io), 34 PE6 (io), 35 PE7 (io), 36 NC., 37 PE2 (io), 38 PE3 (io), 39 PB1 (io), 40 PB2 (io), 41 PD2 (io), 42 PD3 (io), 43 PB3 (io), 44 PB4 (io), 45 PB5 (io), 46 PB6 (io), 47 PB7 (io), 48 NC.

## CH531N
designator U?
8 bit RISC MCU with USB host & device
footprint SOP8 (Footprint not found)
pins: 1 UD+ (io), 2 UD- (io), 3 GND (power), 4 PA6 (io), 5 VDD (power), 6 PA7 (io), 7 PC0 (in), 8 V3 (power)

## CH531S
designator U?
8 bit RISC MCU with USB host & device
footprint ESSOP10 (Footprint not found)
pins: 0 GND (power), 1 UD+ (io), 2 UD- (io), 3 GND (power), 4 PA5 (io), 5 PA0 (in), 6 PA6 (io), 7 VDD (power), 8 PA7 (io), 9 PC0 (in), 10 V3 (power)

## CH533G
designator U?
8 bit RISC MCU with USB host & device
footprint SOP16
footprint DIP16
pins: 1 RST (in), 2 PA0 (io), 3 PA1 (io), 4 PA2 (io), 5 V3 (power), 6 UD+ (io), 7 UD- (io), 8 GND (power), 9 XI (in), 10 XO (out), 11 PB3 (io), 12 PB5 (io), 13 PB6 (io), 14 PB7 (io), 15 VCC (power), 16 PA4 (io)

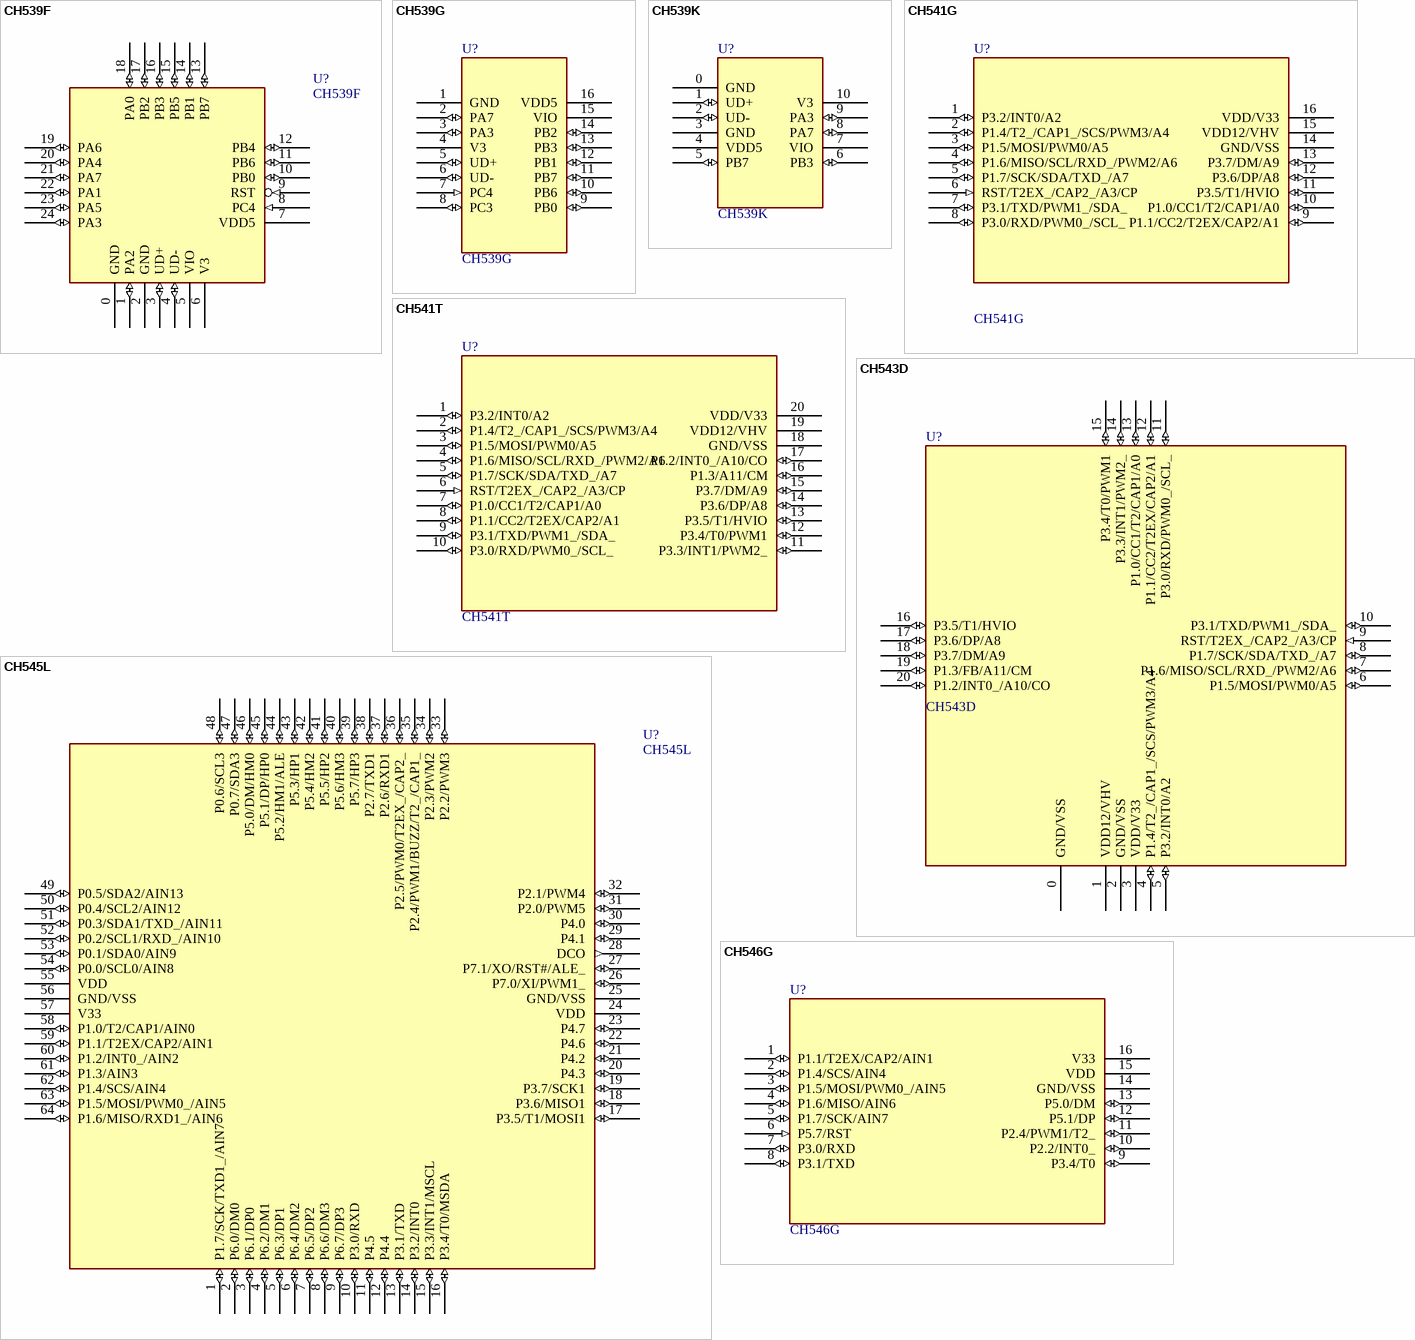
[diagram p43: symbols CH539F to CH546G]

## CH539F
designator U?
8 bit RISC MCU with USB host & device & UART
footprint QFN24_4X4
pins: 0 GND (power), 1 PA2 (io), 2 GND (power), 3 UD+ (io), 4 UD- (io), 5 VIO (power), 6 V3 (power), 7 VDD5 (power), 8 PC4 (in), 9 RST (in), 10 PB0 (io), 11 PB6 (io), 12 PB4 (io), 13 PB7 (io), 14 PB1 (io), 15 PB5 (io), 16 PB3 (io), 17 PB2 (io), 18 PA0 (io), 19 PA6 (io), 20 PA4 (io), 21 PA7 (io), 22 PA1 (io), 23 PA5 (io), 24 PA3 (io)

## CH539G
designator U?
8 bit RISC MCU with USB host & device & UART
footprint SOP16
footprint DIP16
pins: 1 GND (power), 2 PA7 (io), 3 PA3 (io), 4 V3 (power), 5 UD+ (io), 6 UD- (io), 7 PC4 (in), 8 PC3 (io), 9 PB0 (io), 10 PB6 (io), 11 PB7 (io), 12 PB1 (io), 13 PB3 (io), 14 PB2 (io), 15 VIO (power), 16 VDD5 (power)

## CH539K
designator U?
8 bit RISC MCU with USB host & device & UART
footprint ESSOP10
pins: 0 GND (power), 1 UD+ (io), 2 UD- (io), 3 GND (power), 4 VDD5 (power), 5 PB7 (io), 6 PB3 (io), 7 VIO (power), 8 PA7 (io), 9 PA3 (io), 10 V3 (power)

## CH541G
designator U?
8bit MCS51 MCU with USB device & type C & ADC & UART & SPI & I2C & PWM
footprint SOP16 (Footprint not found)
pins: 1 P3.2/INT0/A2 (io), 2 P1.4/T2_/CAP1_/SCS/PWM3/A4 (io), 3 P1.5/MOSI/PWM0/A5 (io), 4 P1.6/MISO/SCL/RXD_/PWM2/A6 (io), 5 P1.7/SCK/SDA/TXD_/A7 (io), 6 RST/T2EX_/CAP2_/A3/CP (in), 7 P3.1/TXD/PWM1_/SDA_ (io), 8 P3.0/RXD/PWM0_/SCL_ (io), 9 P1.1/CC2/T2EX/CAP2/A1 (io), 10 P1.0/CC1/T2/CAP1/A0 (io), 11 P3.5/T1/HVIO (io), 12 P3.6/DP/A8 (io), 13 P3.7/DM/A9 (io), 14 GND/VSS (power), 15 VDD12/VHV (power), 16 VDD/V33 (power)

## CH541T
designator U?
8bit MCS51 MCU with USB device & type C & ADC & UART & SPI & I2C & PWM
footprint TSSOP20
footprint DIP20
pins: 1 P3.2/INT0/A2 (io), 2 P1.4/T2_/CAP1_/SCS/PWM3/A4 (io), 3 P1.5/MOSI/PWM0/A5 (io), 4 P1.6/MISO/SCL/RXD_/PWM2/A6 (io), 5 P1.7/SCK/SDA/TXD_/A7 (io), 6 RST/T2EX_/CAP2_/A3/CP (in), 7 P1.0/CC1/T2/CAP1/A0 (io), 8 P1.1/CC2/T2EX/CAP2/A1 (io), 9 P3.1/TXD/PWM1_/SDA_ (io), 10 P3.0/RXD/PWM0_/SCL_ (io), 11 P3.3/INT1/PWM2_ (io), 12 P3.4/T0/PWM1 (io), 13 P3.5/T1/HVIO (io), 14 P3.6/DP/A8 (io), 15 P3.7/DM/A9 (io), 16 P1.3/A11/CM (io), 17 P1.2/INT0_/A10/CO (io), 18 GND/VSS (power), 19 VDD12/VHV (power), 20 VDD/V33 (power)

## CH543D
designator U?
8bit MCS51 MCU with USB & USB PD & type-C & ADC & UART & SPI & I2C & PWM
footprint QFN20_3X3
pins: 0 GND/VSS (power), 1 VDD12/VHV (power), 2 GND/VSS (power), 3 VDD/V33 (power), 4 P1.4/T2_/CAP1_/SCS/PWM3/A4 (io), 5 P3.2/INT0/A2 (io), 6 P1.5/MOSI/PWM0/A5 (io), 7 P1.6/MISO/SCL/RXD_/PWM2/A6 (io), 8 P1.7/SCK/SDA/TXD_/A7 (io), 9 RST/T2EX_/CAP2_/A3/CP (in), 10 P3.1/TXD/PWM1_/SDA_ (io), 11 P3.0/RXD/PWM0_/SCL_ (io), 12 P1.1/CC2/T2EX/CAP2/A1 (io), 13 P1.0/CC1/T2/CAP1/A0 (io), 14 P3.3/INT1/PWM2_ (io), 15 P3.4/T0/PWM1 (io), 16 P3.5/T1/HVIO (io), 17 P3.6/DP/A8 (io), 18 P3.7/DM/A9 (io), 19 P1.3/FB/A11/CM (io), 20 P1.2/INT0_/A10/CO (io)

## CH545L
designator U?
8bit MCS51 MCU with ADC & USB host 4 ports & KVM4 device & dual UART & SPI & quad I2C
footprint LQFP64
pins: 1 P1.7/SCK/TXD1_/AIN7 (io), 2 P6.0/DM0 (io), 3 P6.1/DP0 (io), 4 P6.2/DM1 (io), 5 P6.3/DP1 (io), 6 P6.4/DM2 (io), 7 P6.5/DP2 (io), 8 P6.6/DM3 (io), 9 P6.7/DP3 (io), 10 P3.0/RXD (io), 11 P4.5 (io), 12 P4.4 (io), 13 P3.1/TXD (io), 14 P3.2/INT0 (io), 15 P3.3/INT1/MSCL (io), 16 P3.4/T0/MSDA (io), 17 P3.5/T1/MOSI1 (io), 18 P3.6/MISO1 (io), 19 P3.7/SCK1 (io), 20 P4.3 (io), 21 P4.2 (io), 22 P4.6 (io), 23 P4.7 (io), 24 VDD (power), 25 GND/VSS (power), 26 P7.0/XI/PWM1_ (io), 27 P7.1/XO/RST#/ALE_ (io), 28 DCO (out), 29 P4.1 (io), 30 P4.0 (io), 31 P2.0/PWM5 (io), 32 P2.1/PWM4 (io), 33 P2.2/PWM3 (io), 34 P2.3/PWM2 (io), 35 P2.4/PWM1/BUZZ/T2_/CAP1_ (io), 36 P2.5/PWM0/T2EX_/CAP2_ (io), 37 P2.6/RXD1 (io), 38 P2.7/TXD1 (io), 39 P5.7/HP3 (io), 40 P5.6/HM3 (io), 41 P5.5/HP2 (io), 42 P5.4/HM2 (io), 43 P5.3/HP1 (io), 44 P5.2/HM1/ALE (io), 45 P5.1/DP/HP0 (io), 46 P5.0/DM/HM0 (io), 47 P0.7/SDA3 (io), 48 P0.6/SCL3 (io), 49 P0.5/SDA2/AIN13 (io), 50 P0.4/SCL2/AIN12 (io), 51 P0.3/SDA1/TXD_/AIN11 (io), 52 P0.2/SCL1/RXD_/AIN10 (io), 53 P0.1/SDA0/AIN9 (io), 54 P0.0/SCL0/AIN8 (io), 55 VDD (power), 56 GND/VSS (power), 57 V33 (power), 58 P1.0/T2/CAP1/AIN0 (io), 59 P1.1/T2EX/CAP2/AIN1 (io), 60 P1.2/INT0_/AIN2 (io), 61 P1.3/AIN3 (io), 62 P1.4/SCS/AIN4 (io), 63 P1.5/MOSI/PWM0_/AIN5 (io), 64 P1.6/MISO/RXD1_/AIN6 (io)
